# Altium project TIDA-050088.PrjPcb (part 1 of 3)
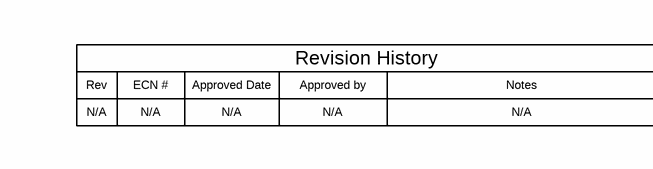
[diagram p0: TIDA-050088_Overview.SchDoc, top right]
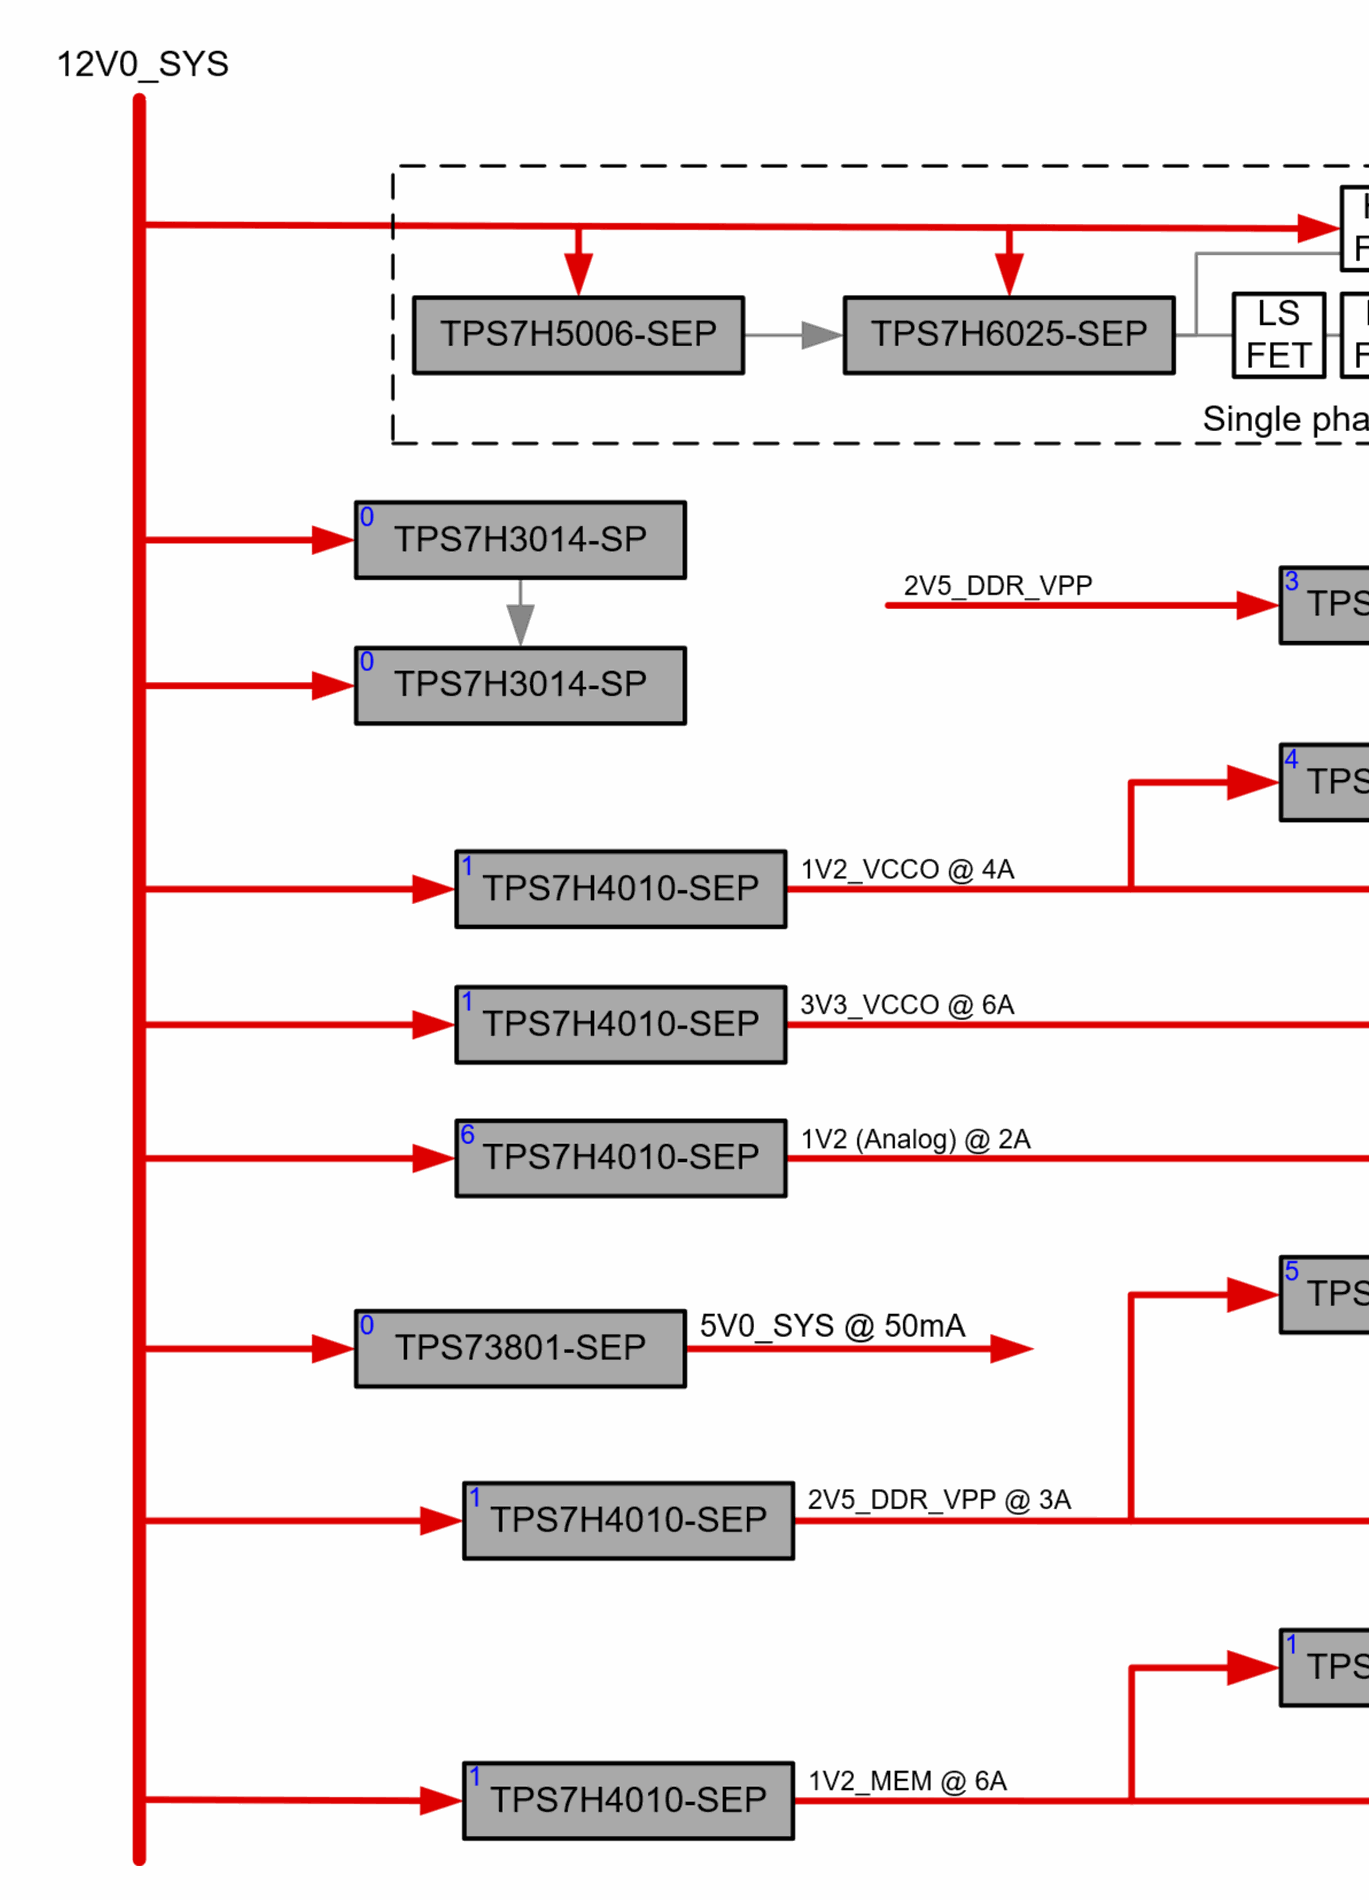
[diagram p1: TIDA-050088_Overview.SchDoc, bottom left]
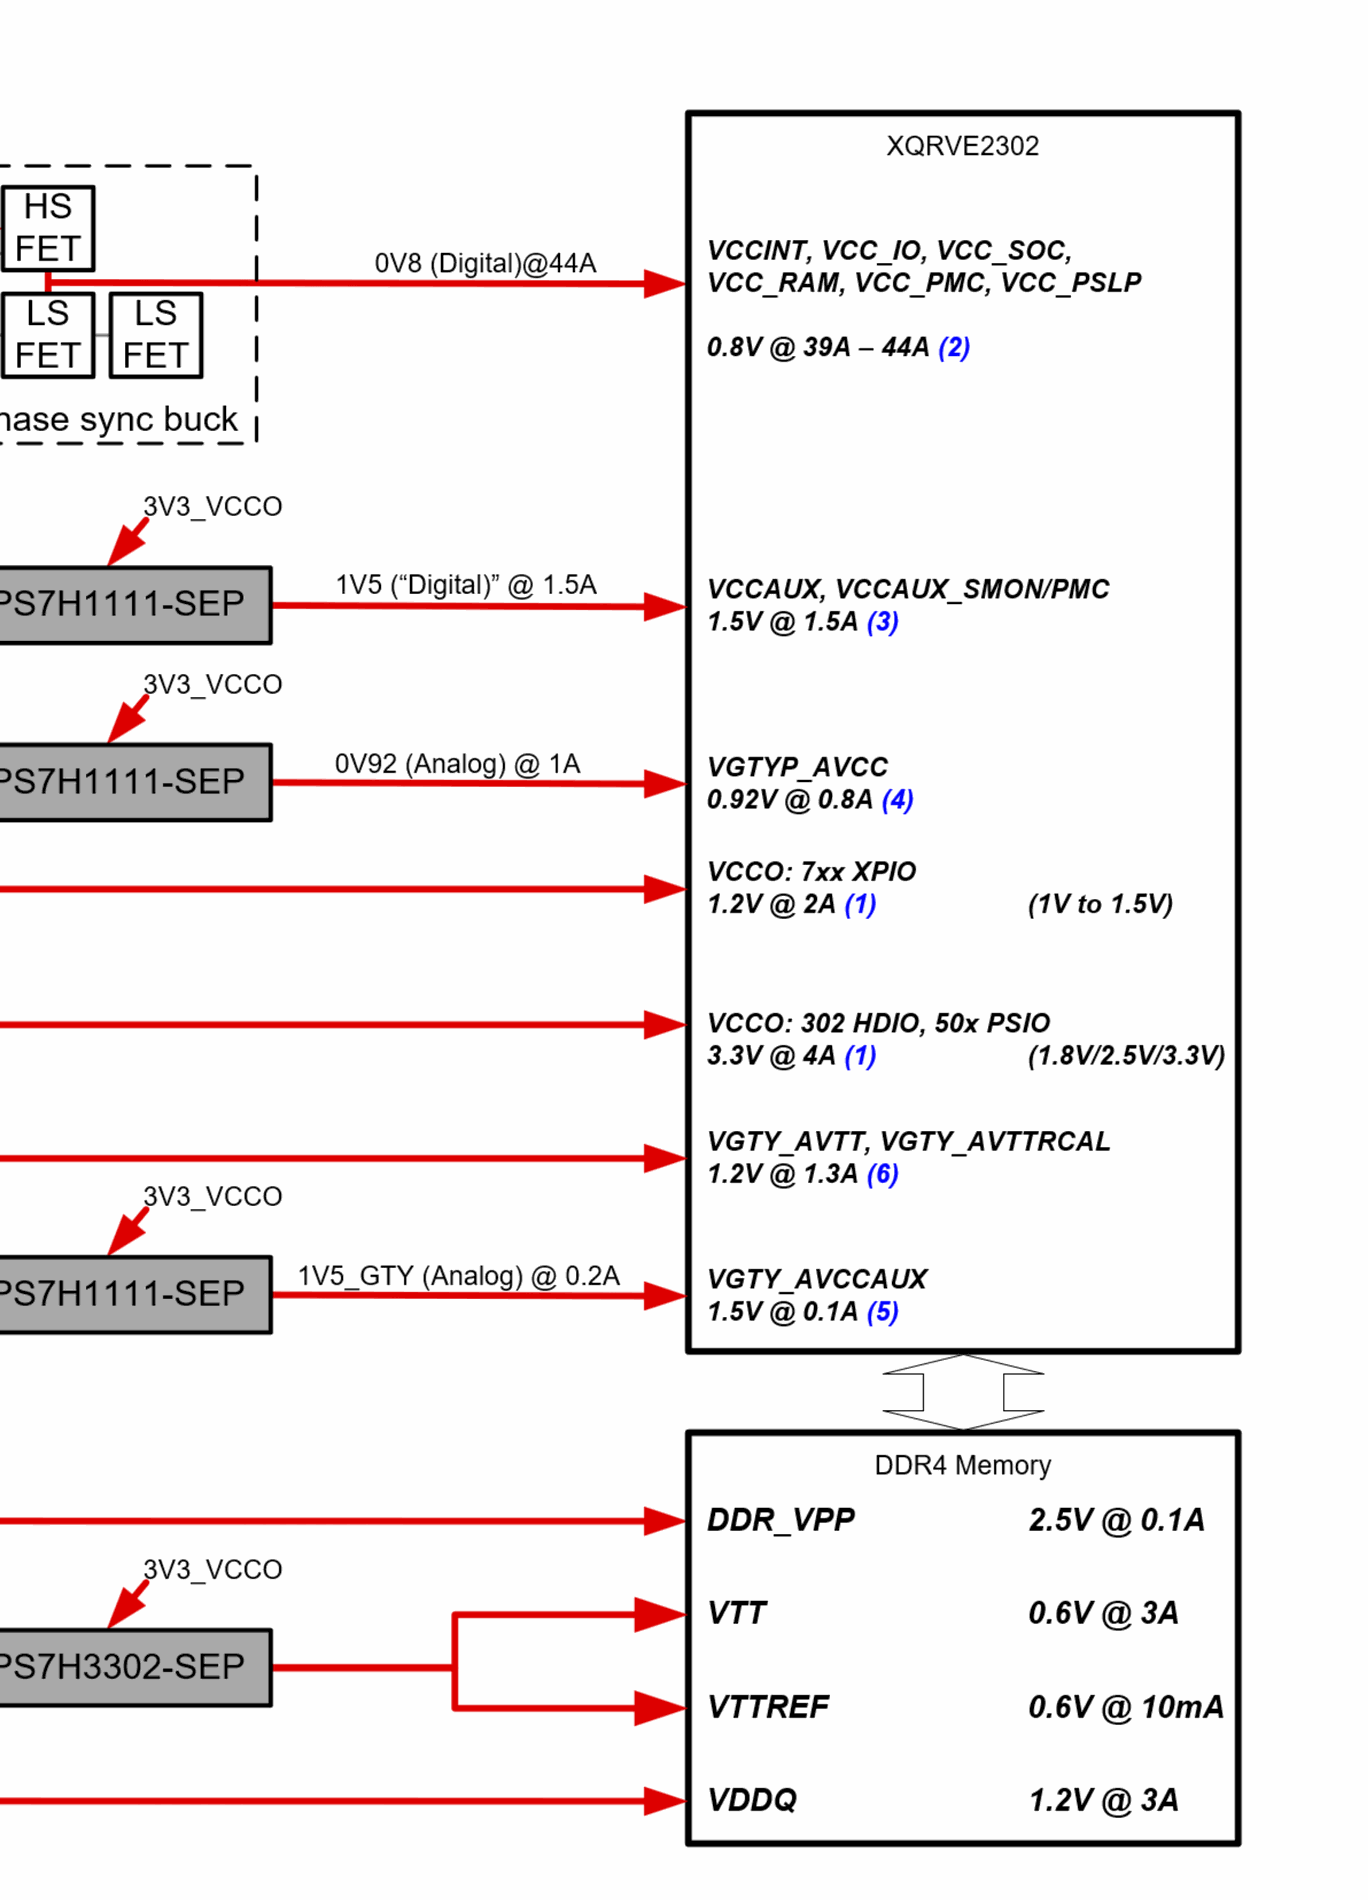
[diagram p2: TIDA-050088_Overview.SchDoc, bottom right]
CopyrightYear: 2024; DrawnBy: Kyle Rakos; PCB_Layout: Kyle Rakos; PCB_Rev: A; PRJ_Customer: Public Release; PRJ_Engineer: Kyle Rakos; PRJ_Number: TIDA-050088; PRJ_Title: Versal AI Edge XQRVE2302 Power; SCH_Rev: A; TechSupport: http://www.ti.com/support; TID: 050088; Versal AI Edge XQRVE2302 Power: EdgePower
7 sheets, 539 parts. Net scope: global (net labels, ports and power ports of the same name join across sheets).
Board file: TIDA-050088_PCB.PcbDoc
Sheets:
  TIDA-050088_Overview.SchDoc
  TIDA-050088_Core.SchDoc
  TIDA-050088_Sequencing.SchDoc
  TIDA-050088_LDOs.SchDoc
  TIDA-050088_Bucks.SchDoc
  TIDA-050088_Aux.SchDoc
  TIDA-050088_Hardware.SchDoc

## Sheet TIDA-050088_Overview.SchDoc
size 558 x 431 mm; Date: Not shown in title block; ApprovedBy: Not shown in title block; CheckedBy: Not shown in title block; Author: Not shown in title block; CompanyName: Not shown in title block; Engineer: Not shown in title block; Organization: Not shown in title block; Address1: Not shown in title block; Address2: Not shown in title block; Address3: Not shown in title block; Address4: Not shown in title block; DocumentNumber: 1; Revision: Use project parameter SCH_Rev; SheetNumber: 1; SheetTotal: 7; PageSetup: Record=PageOptions¦CenterHorizontal=True¦CenterVertical=True¦PrintScale=1.00¦XCorrection=1.00¦YCorrection=1.00¦PrintKind=0¦BorderSize=5000000¦LeftOffset=0¦BottomOffset=0¦Orientation=2¦PaperLength=1000¦PaperWidth=1000¦Scale=100¦PaperSource=15¦PrintQuality=600¦MediaType=1¦DitherType=10¦PaperKind=Letter¦PrintScaleMode=1

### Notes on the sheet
- Rev
- N/A
- ECN #
- Approved Date
- Approved by
- Revision History
- Notes

## Sheet TIDA-050088_Core.SchDoc
size 558 x 431 mm; Date: Not shown in title block; ApprovedBy: Not shown in title block; CheckedBy: Not shown in title block; Author: Not shown in title block; CompanyName: Not shown in title block; Engineer: Not shown in title block; Organization: Not shown in title block; Address1: Not shown in title block; Address2: Not shown in title block; Address3: Not shown in title block; Address4: Not shown in title block; DocumentNumber: 2; Revision: Use project parameter SCH_Rev; SheetNumber: 2; SheetTotal: 7; PageSetup: Record=PageOptions¦CenterHorizontal=True¦CenterVertical=True¦PrintScale=1.00¦XCorrection=1.00¦YCorrection=1.00¦PrintKind=0¦BorderSize=5000000¦LeftOffset=0¦BottomOffset=0¦Orientation=2¦PaperLength=1000¦PaperWidth=1000¦Scale=100¦PaperSource=15¦PrintQuality=600¦MediaType=1¦DitherType=10¦PaperKind=Letter¦PrintScaleMode=1
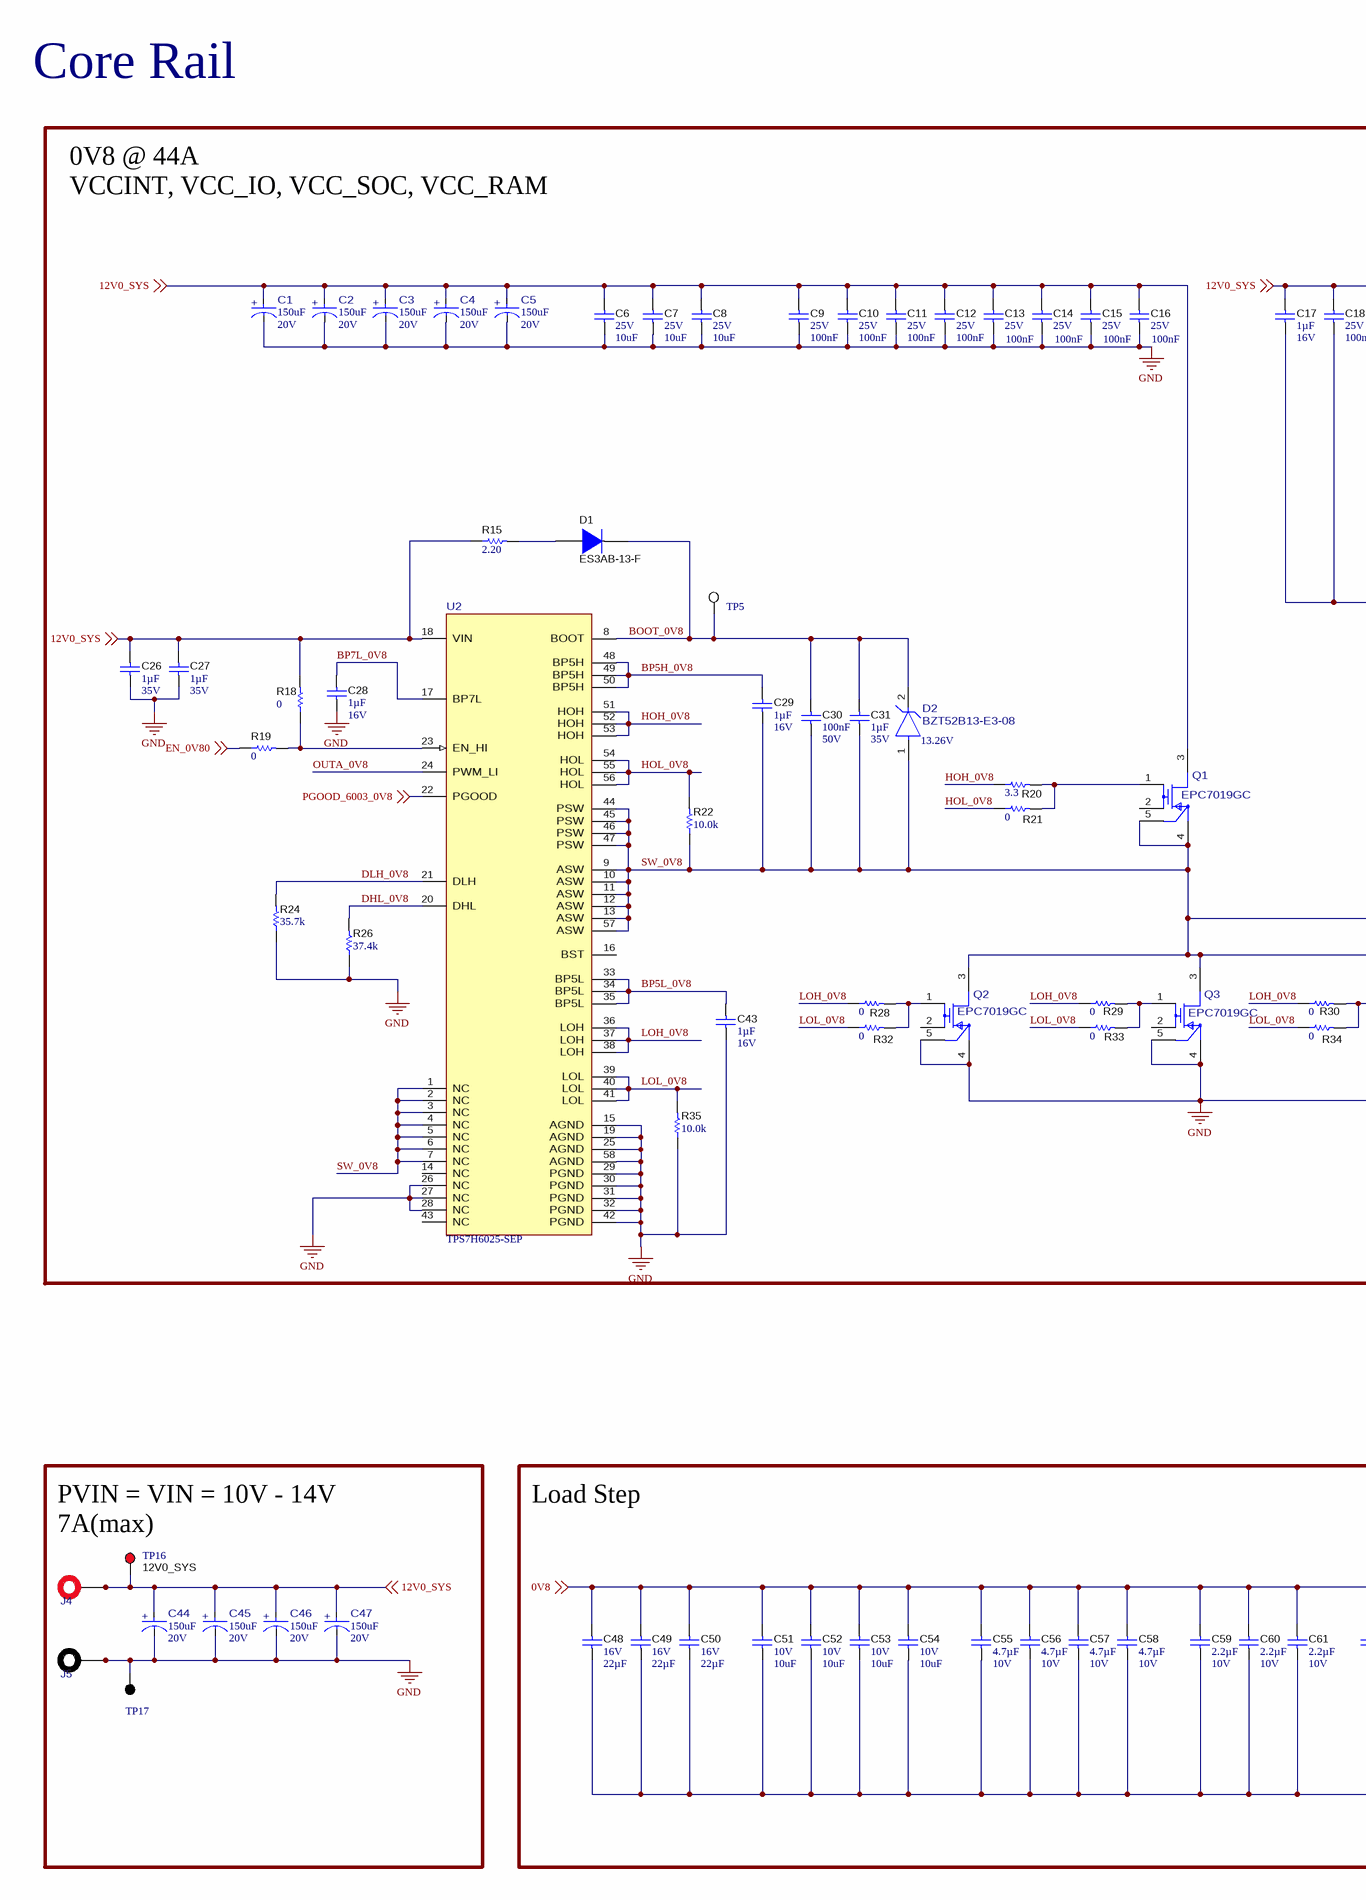
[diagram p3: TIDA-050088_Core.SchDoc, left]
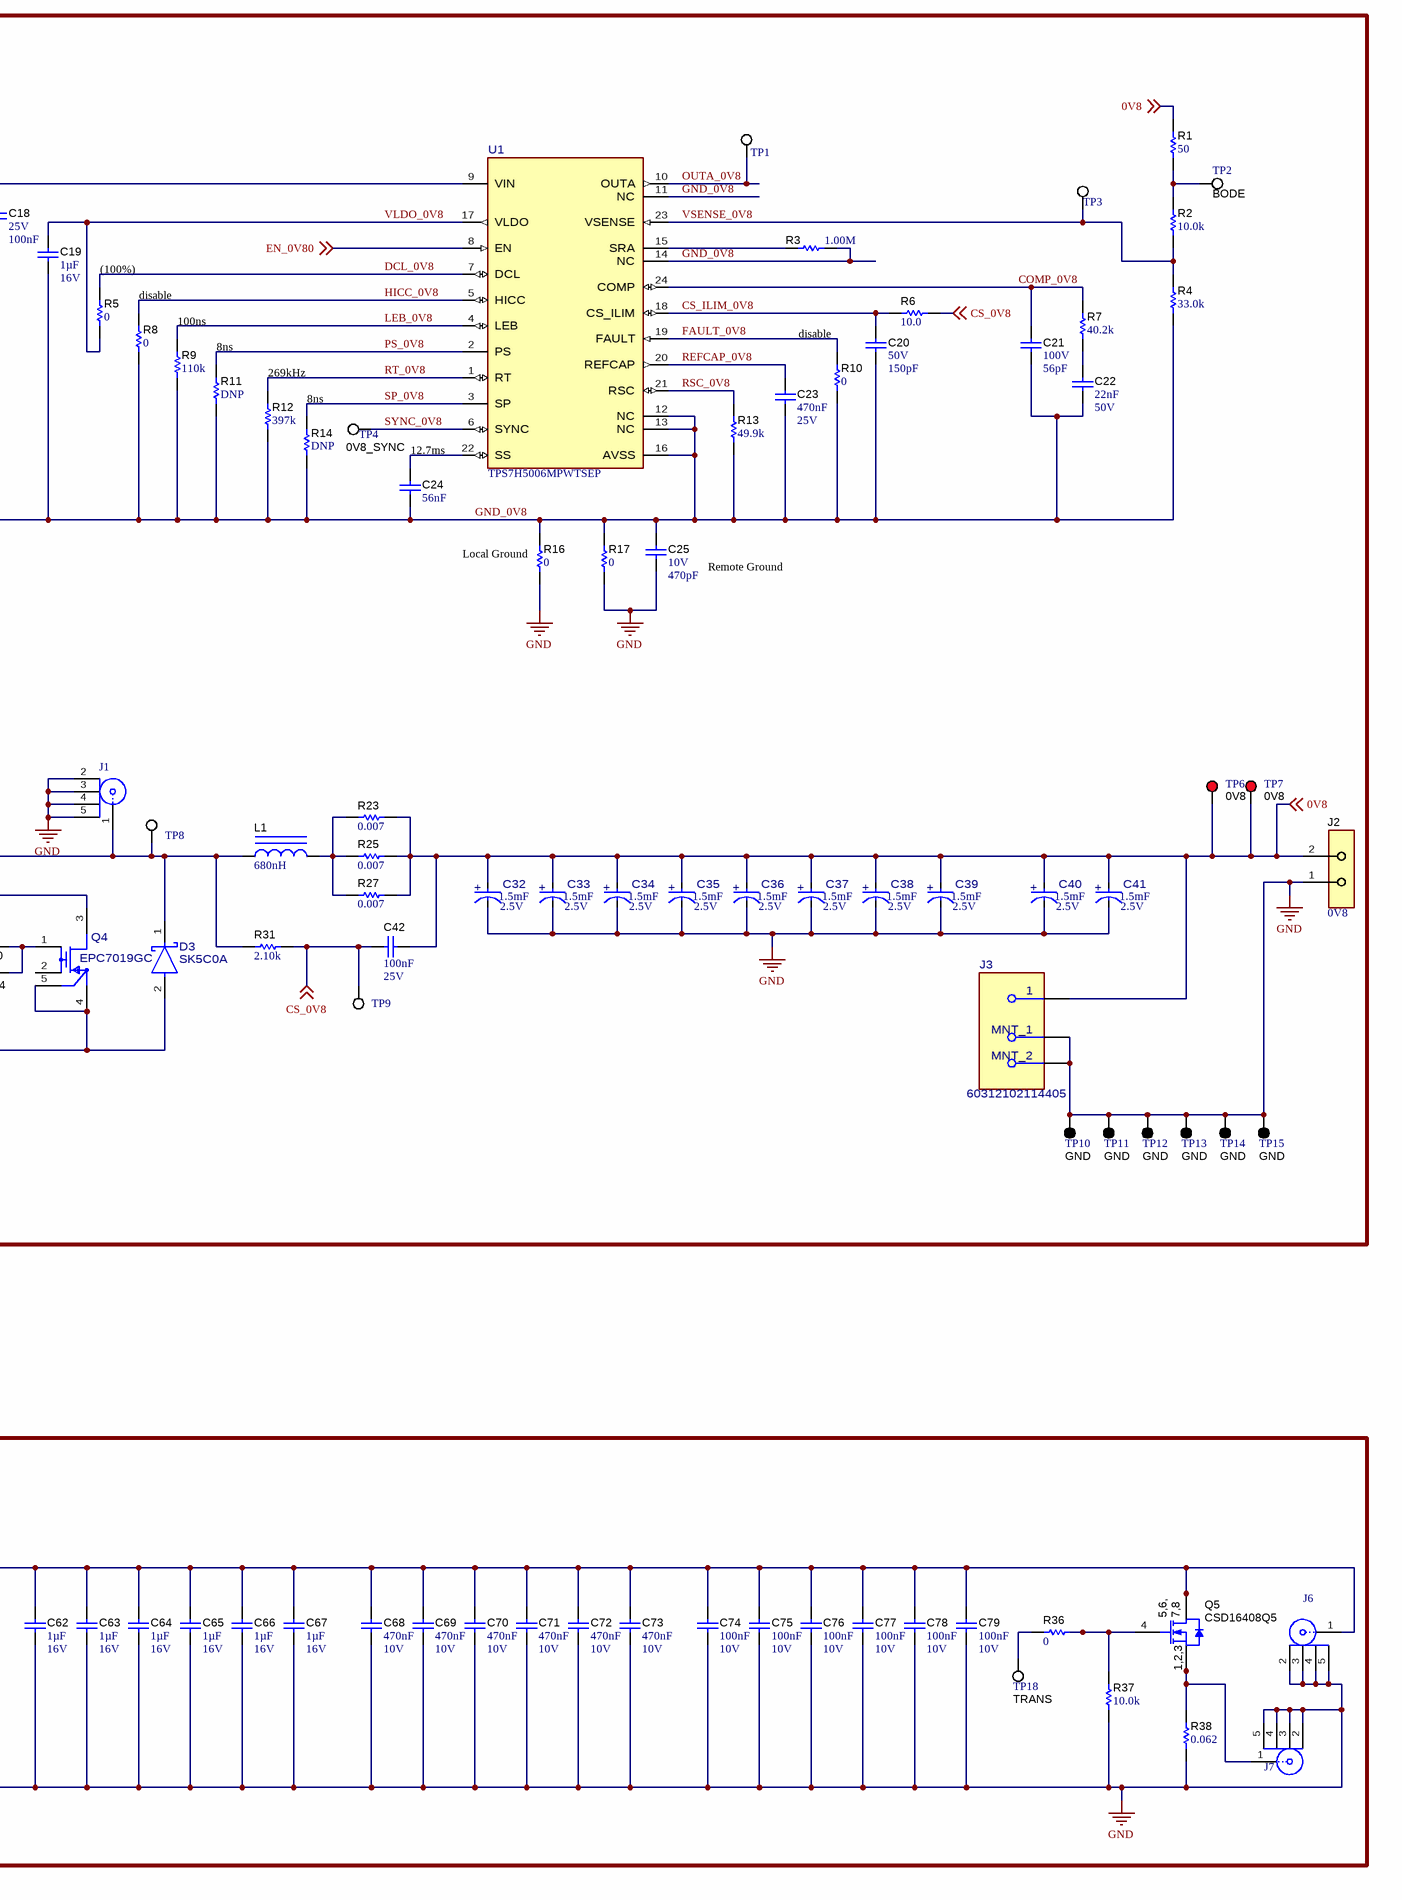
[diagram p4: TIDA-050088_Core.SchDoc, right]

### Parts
C1  ValueDisplayed: 150uF  VDC_V: 20V  [FP-T521D157M020ATE050_2917-MFG]  (hidden comment: T521D157M020ATE050)
C2  ValueDisplayed: 150uF  VDC_V: 20V  [FP-T521D157M020ATE050_2917-MFG]  (hidden comment: T521D157M020ATE050)
C3  ValueDisplayed: 150uF  VDC_V: 20V  [FP-T521D157M020ATE050_2917-MFG]  (hidden comment: T521D157M020ATE050)
C4  ValueDisplayed: 150uF  VDC_V: 20V  [FP-T521D157M020ATE050_2917-MFG]  (hidden comment: T521D157M020ATE050)
C5  ValueDisplayed: 150uF  VDC_V: 20V  [FP-T521D157M020ATE050_2917-MFG]  (hidden comment: T521D157M020ATE050)
C6  VDC_V: 25V  ValueDisplayed: 10uF  [1210_280]  (hidden comment: GCM32ER71E106KA57L)
C7  VDC_V: 25V  ValueDisplayed: 10uF  [1210_280]  (hidden comment: GCM32ER71E106KA57L)
C8  VDC_V: 25V  ValueDisplayed: 10uF  [1210_280]  (hidden comment: GCM32ER71E106KA57L)
C9  VDC_V: 25V  Cap_F: 100nF  [0603]  (hidden comment: GCM188R71E104KA57D)
C10  VDC_V: 25V  Cap_F: 100nF  [0603]  (hidden comment: GCM188R71E104KA57D)
C11  VDC_V: 25V  Cap_F: 100nF  [0603]  (hidden comment: GCM188R71E104KA57D)
C12  VDC_V: 25V  Cap_F: 100nF  [0603]  (hidden comment: GCM188R71E104KA57D)
C13  VDC_V: 25V  Cap_F: 100nF  [0603]  (hidden comment: GCM188R71E104KA57D)
C14  VDC_V: 25V  Cap_F: 100nF  [0603]  (hidden comment: GCM188R71E104KA57D)
C15  VDC_V: 25V  Cap_F: 100nF  [0603]  (hidden comment: GCM188R71E104KA57D)
C16  VDC_V: 25V  Cap_F: 100nF  [0603]  (hidden comment: GCM188R71E104KA57D)
C17  Cap_F: 1µF  VDC_V: 16V  [0805_HV]  (hidden comment: C0805C105K4RACAUTO)
C18  VDC_V: 25V  Cap_F: 100nF  [0603]  (hidden comment: GCM188R71E104KA57D)
C19  Cap_F: 1µF  VDC_V: 16V  [0805_HV]  (hidden comment: C0805C105K4RACAUTO)
C20  VDC_V: 50V  ValueDisplayed: 150pF  [0603]  (hidden comment: C0603C151J5GACTU)
C21  VDC_V: 100V  ValueDisplayed: 56pF  [0603]  (hidden comment: GRM1885C2A560JA01D)
C22  Cap_F: 22nF  VDC_V: 50V  [0603]  (hidden comment: C0603C223K5RACTU)
C23  Cap_F: 470nF  VDC_V: 25V  [0603]  (hidden comment: GCM188R71E474KA64D)
C24  Cap_F: 56nF  [0603]  (hidden comment: 06035C563KAT2A)
C25  VDC_V: 10V  ValueDisplayed: 470pF  [0603]  (hidden comment: 885012006012)
C26  Cap_F: 1µF  VDC_V: 35V  [0805_HV]  (hidden comment: GRM219R7YA105KA12D)
C27  Cap_F: 1µF  VDC_V: 35V  [0805_HV]  (hidden comment: GRM219R7YA105KA12D)
C28  Cap_F: 1µF  VDC_V: 16V  [0805_HV]  (hidden comment: C0805C105K4RACAUTO)
C29  Cap_F: 1µF  VDC_V: 16V  [0805_HV]  (hidden comment: C0805C105K4RACAUTO)
C30  Cap_F: 100nF  VDC_V: 50V  [0603]  (hidden comment: 06035C104KAZ2A)
C31  Cap_F: 1µF  VDC_V: 35V  [0805_HV]  (hidden comment: GRM219R7YA105KA12D)
C32  ValueDisplayed: 1.5mF  VDC_V: 2.5V  [FP-T520X158M2R5ATE015_2917-MFG]  (hidden comment: T520X158M2R5ATE015)
C33  ValueDisplayed: 1.5mF  VDC_V: 2.5V  [FP-T520X158M2R5ATE015_2917-MFG]  (hidden comment: T520X158M2R5ATE015)
C34  ValueDisplayed: 1.5mF  VDC_V: 2.5V  [FP-T520X158M2R5ATE015_2917-MFG]  (hidden comment: T520X158M2R5ATE015)
C35  ValueDisplayed: 1.5mF  VDC_V: 2.5V  [FP-T520X158M2R5ATE015_2917-MFG]  (hidden comment: T520X158M2R5ATE015)
C36  ValueDisplayed: 1.5mF  VDC_V: 2.5V  [FP-T520X158M2R5ATE015_2917-MFG]  (hidden comment: T520X158M2R5ATE015)
C37  ValueDisplayed: 1.5mF  VDC_V: 2.5V  [FP-T520X158M2R5ATE015_2917-MFG]  (hidden comment: T520X158M2R5ATE015)
C38  ValueDisplayed: 1.5mF  VDC_V: 2.5V  [FP-T520X158M2R5ATE015_2917-MFG]  (hidden comment: T520X158M2R5ATE015)
C39  ValueDisplayed: 1.5mF  VDC_V: 2.5V  [FP-T520X158M2R5ATE015_2917-MFG]  (hidden comment: T520X158M2R5ATE015)
C40  ValueDisplayed: 1.5mF  VDC_V: 2.5V  [FP-T520X158M2R5ATE015_2917-MFG]  (hidden comment: T520X158M2R5ATE015)
C41  ValueDisplayed: 1.5mF  VDC_V: 2.5V  [FP-T520X158M2R5ATE015_2917-MFG]  (hidden comment: T520X158M2R5ATE015)
C42  Cap_F: 100nF  VDC_V: 25V  [0603]  (hidden comment: C0603X104K3RACTU)
C43  Cap_F: 1µF  VDC_V: 16V  [0805_HV]  (hidden comment: C0805C105K4RACAUTO)
C44  ValueDisplayed: 150uF  VDC_V: 20V  [FP-T521D157M020ATE050_2917-MFG]  (hidden comment: T521D157M020ATE050)
C45  ValueDisplayed: 150uF  VDC_V: 20V  [FP-T521D157M020ATE050_2917-MFG]  (hidden comment: T521D157M020ATE050)
C46  ValueDisplayed: 150uF  VDC_V: 20V  [FP-T521D157M020ATE050_2917-MFG]  (hidden comment: T521D157M020ATE050)
C47  ValueDisplayed: 150uF  VDC_V: 20V  [FP-T521D157M020ATE050_2917-MFG]  (hidden comment: T521D157M020ATE050)
C48  VDC_V: 16V  ValueDisplayed: 22µF  [1210_270]  (hidden comment: CL32B226KOJNFNE)
C49  VDC_V: 16V  ValueDisplayed: 22µF  [1210_270]  (hidden comment: CL32B226KOJNFNE)
C50  VDC_V: 16V  ValueDisplayed: 22µF  [1210_270]  (hidden comment: CL32B226KOJNFNE)
C51  VDC_V: 10V  ValueDisplayed: 10uF  [1206]  (hidden comment: C3216X7R1A106K085AC)
C52  VDC_V: 10V  ValueDisplayed: 10uF  [1206]  (hidden comment: C3216X7R1A106K085AC)
C53  VDC_V: 10V  ValueDisplayed: 10uF  [1206]  (hidden comment: C3216X7R1A106K085AC)
C54  VDC_V: 10V  ValueDisplayed: 10uF  [1206]  (hidden comment: C3216X7R1A106K085AC)
C55  Cap_F: 4.7µF  VDC_V: 10V  [0805_HV]  (hidden comment: 885012207025)
C56  Cap_F: 4.7µF  VDC_V: 10V  [0805_HV]  (hidden comment: 885012207025)
C57  Cap_F: 4.7µF  VDC_V: 10V  [0805_HV]  (hidden comment: 885012207025)
C58  Cap_F: 4.7µF  VDC_V: 10V  [0805_HV]  (hidden comment: 885012207025)
C59  Cap_F: 2.2µF  VDC_V: 10V  [0805_HV]  (hidden comment: GRM21BR71A225KA01L)
C60  Cap_F: 2.2µF  VDC_V: 10V  [0805_HV]  (hidden comment: GRM21BR71A225KA01L)
C61  Cap_F: 2.2µF  VDC_V: 10V  [0805_HV]  (hidden comment: GRM21BR71A225KA01L)
C62  Cap_F: 1µF  VDC_V: 16V  [0805_HV]  (hidden comment: C0805C105K4RACAUTO)
C63  Cap_F: 1µF  VDC_V: 16V  [0805_HV]  (hidden comment: C0805C105K4RACAUTO)
C64  Cap_F: 1µF  VDC_V: 16V  [0805_HV]  (hidden comment: C0805C105K4RACAUTO)
C65  Cap_F: 1µF  VDC_V: 16V  [0805_HV]  (hidden comment: C0805C105K4RACAUTO)
C66  Cap_F: 1µF  VDC_V: 16V  [0805_HV]  (hidden comment: C0805C105K4RACAUTO)
C67  Cap_F: 1µF  VDC_V: 16V  [0805_HV]  (hidden comment: C0805C105K4RACAUTO)
C68  Cap_F: 470nF  VDC_V: 10V  [0603]  (hidden comment: C0603C474K8RACTU)
C69  Cap_F: 470nF  VDC_V: 10V  [0603]  (hidden comment: C0603C474K8RACTU)
C70  Cap_F: 470nF  VDC_V: 10V  [0603]  (hidden comment: C0603C474K8RACTU)
C71  Cap_F: 470nF  VDC_V: 10V  [0603]  (hidden comment: C0603C474K8RACTU)
C72  Cap_F: 470nF  VDC_V: 10V  [0603]  (hidden comment: C0603C474K8RACTU)
C73  Cap_F: 470nF  VDC_V: 10V  [0603]  (hidden comment: C0603C474K8RACTU)
C74  Cap_F: 100nF  VDC_V: 10V  [0603]  (hidden comment: 885012206020)
C75  Cap_F: 100nF  VDC_V: 10V  [0603]  (hidden comment: 885012206020)
C76  Cap_F: 100nF  VDC_V: 10V  [0603]  (hidden comment: 885012206020)
C77  Cap_F: 100nF  VDC_V: 10V  [0603]  (hidden comment: 885012206020)
C78  Cap_F: 100nF  VDC_V: 10V  [0603]  (hidden comment: 885012206020)
C79  Cap_F: 100nF  VDC_V: 10V  [0603]  (hidden comment: 885012206020)
D1  ES3AB-13-F  [SMB]
D2  BZT52B13-E3-08  Vf_V: 13.26V  [FP-BZT52B13-E3-08_SOD123-MFG]
D3  SK5C0A  [FP-SK5C0A_SMA-MFG]
J1  SW  [Tek_131-5031-00]  (value not drawn)
J2  Silkscreen: 0V8  [FP-1929517_HDR2-MFG]  (hidden comment: 1929517)
J3  60312102114405  [FP-60312102114405_CONN_SMA-MFG]
J4  571-0500  [571-0500]  (value not drawn)
J5  571-0100  [571-0100]  (value not drawn)
J6  0V8  [Tek_131-5031-00]  (value not drawn)
J7  ISTEP  [Tek_131-5031-00]  (value not drawn)
L1  ValueDisplayed: 680nH  [XAL1010]  (hidden comment: XAL1010-681MEB)
Q1  EPC7019GC  [FP-EPC7019GC_FSMD-G-MFG]
Q2  EPC7019GC  [FP-EPC7019GC_FSMD-G-MFG]
Q3  EPC7019GC  [FP-EPC7019GC_FSMD-G-MFG]
Q4  EPC7019GC  [FP-EPC7019GC_FSMD-G-MFG]
Q5  CSD16408Q5  [DQH0008A]
R1  ValueDisplayed: 50  [0603]  (hidden comment: FC0603E50R0BTBST1)
R2  ValueDisplayed: 10.0k  [0603]  (hidden comment: PHT0603Y1002BGT200)
R3  ValueDisplayed: 1.00M  [0603]  (hidden comment: CRCW06031M00FKEA)
R4  ValueDisplayed: 33.0k  [0603]  (hidden comment: RG1608P-333-B-T5)
R5  ValueDisplayed: 0  [0603]  (hidden comment: RCS06030000Z0EA)
R6  ValueDisplayed: 10.0  [0603]  (hidden comment: TNPW060310R0BEEA)
R7  ValueDisplayed: 40.2k  [0603]  (hidden comment: RT0603BRD0740K2L)
R8  ValueDisplayed: 0  [0603]  (hidden comment: RCS06030000Z0EA)
R9  ValueDisplayed: 110k  [0603]  (hidden comment: RG1608P-114-B-T5)
R10  ValueDisplayed: 0  [0603]  (hidden comment: RCS06030000Z0EA)
R11  ValueDisplayed: DNP  [0603]  (hidden comment: RN73H1JTTD3973F25)
R12  ValueDisplayed: 397k  [0603]  (hidden comment: RN73H1JTTD3973F25)
R13  ValueDisplayed: 49.9k  [0603]  (hidden comment: RT0603BRD0749K9L)
R14  ValueDisplayed: DNP  [0603]  (hidden comment: RN73H1JTTD3973F25)
R15  ValueDisplayed: 2.20  [0603]  (hidden comment: ERJ-3RQF2R2V)
R16  ValueDisplayed: 0  [0603]  (hidden comment: RCS06030000Z0EA)
R17  ValueDisplayed: 0  [0603]  (hidden comment: RCS06030000Z0EA)
R18  ValueDisplayed: 0  [0603]  (hidden comment: RCS06030000Z0EA)
R19  ValueDisplayed: 0  [0603]  (hidden comment: RCS06030000Z0EA)
R20  ValueDisplayed: 3.3  [0603]  (hidden comment: CRCW06033R30JNEA)
R21  ValueDisplayed: 0  [0603]  (hidden comment: RCS06030000Z0EA)
R22  ValueDisplayed: 10.0k  [0603]  (hidden comment: PHT0603Y1002BGT200)
R23  ValueDisplayed: 0.007  [2512_WIDE]  (hidden comment: KRL6432E-M-R007-F-T1)
R24  ValueDisplayed: 35.7k  [0603]  (hidden comment: RT0603BRD0735K7L)
R25  ValueDisplayed: 0.007  [2512_WIDE]  (hidden comment: KRL6432E-M-R007-F-T1)
R26  ValueDisplayed: 37.4k  [0603]  (hidden comment: RT0603BRD0737K4L)
R27  ValueDisplayed: 0.007  [2512_WIDE]  (hidden comment: KRL6432E-M-R007-F-T1)
R28  ValueDisplayed: 0  [0603]  (hidden comment: RCS06030000Z0EA)
R29  ValueDisplayed: 0  [0603]  (hidden comment: RCS06030000Z0EA)
R30  ValueDisplayed: 0  [0603]  (hidden comment: RCS06030000Z0EA)
R31  ValueDisplayed: 2.10k  [0603]  (hidden comment: RG1608P-2101-B-T5)
R32  ValueDisplayed: 0  [0603]  (hidden comment: RCS06030000Z0EA)
R33  ValueDisplayed: 0  [0603]  (hidden comment: RCS06030000Z0EA)
R34  ValueDisplayed: 0  [0603]  (hidden comment: RCS06030000Z0EA)
R35  ValueDisplayed: 10.0k  [0603]  (hidden comment: PHT0603Y1002BGT200)
R36  ValueDisplayed: 0  [0603]  (hidden comment: RCS06030000Z0EA)
R37  ValueDisplayed: 10.0k  [0603]  (hidden comment: PHT0603Y1002BGT200)
R38  ValueDisplayed: 0.062  [2512_084]  (hidden comment: PE2512FKF7W0R062L)
TP1  OUTA  [Keystone5012]  (value not drawn)
TP2  BODE  [Keystone5012]
TP3  VSNS  [Keystone5012]  (value not drawn)
TP4  0V8_SYNC  [Keystone5012]
TP5  BOOT  [Keystone5012]  (value not drawn)
TP6  0V8  [Keystone5010]
TP7  0V8  [Keystone5010]
TP8  SW  [Keystone5012]  (value not drawn)
TP9  CS  [Keystone5012]  (value not drawn)
TP10  GND  [Keystone5011]
TP11  GND  [Keystone5011]
TP12  GND  [Keystone5011]
TP13  GND  [Keystone5011]
TP14  GND  [Keystone5011]
TP15  GND  [Keystone5011]
TP16  12V0_SYS  [Keystone5010]
TP17  GND  [Keystone5011]  (value not drawn)
TP18  TRANS  [Keystone5012]
U1  TPS7H5006MPWTSEP  [PW0024A-MFG]
U2  PartNumber: TPS7H6025-SEP  [DCA0056M-MFG]  (hidden comment: PTPS7H6025-SEP)

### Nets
GND: C1.1(CATHODE) C2.1(CATHODE) C3.1(CATHODE) C4.1(CATHODE) C5.1(CATHODE) C6.2 C7.2 C8.2 C9.2 C10.2 C11.2 C12.2 C13.2 C14.2 C15.2 C16.2 C25.2 C26.2 C27.2 C28.2 C32.1(CATHODE) C33.1(CATHODE) C34.1(CATHODE) C35.1(CATHODE) C36.1(CATHODE) C37.1(CATHODE) C38.1(CATHODE) C39.1(CATHODE) C40.1(CATHODE) C41.1(CATHODE) C43.2 C44.1(CATHODE) C45.1(CATHODE) C46.1(CATHODE) C47.1(CATHODE) C48.2 C49.2 C50.2 C51.2 C52.2 C53.2 C54.2 C55.2 C56.2 C57.2 C58.2 C59.2 C60.2 C61.2 C62.2 C63.2 C64.2 C65.2 C66.2 C67.2 C68.2 C69.2 C70.2 C71.2 C72.2 C73.2 C74.2 C75.2 C76.2 C77.2 C78.2 C79.2 D3.2(ANODE) J1.2 J1.3 J1.4 J1.5 J2.1 J3.2(MNT_1) J3.3(MNT_2) J5.1 J5.2 J6.2 J6.3 J6.4 J6.5 J7.2 J7.3 J7.4 J7.5 Q2.4(S) Q2.5(SS) Q3.4(S) Q3.5(SS) Q4.4(S) Q4.5(SS) R16.1 R17.1 R24.1 R26.1 R35.1 R37.1 R38.1 TP10.1 TP11.1 TP12.1 TP13.1 TP14.1 TP15.1 TP17.1 U2.15(AGND) U2.19(AGND) U2.25(AGND) U2.26(NC) U2.27(NC) U2.28(NC) U2.29(PGND) U2.30(PGND) U2.31(PGND) U2.32(PGND) U2.42(PGND) U2.58(AGND)
0V8: C32.2(ANODE) C33.2(ANODE) C34.2(ANODE) C35.2(ANODE) C36.2(ANODE) C37.2(ANODE) C38.2(ANODE) C39.2(ANODE) C40.2(ANODE) C41.2(ANODE) C42.1 C48.1 C49.1 C50.1 C51.1 C52.1 C53.1 C54.1 C55.1 C56.1 C57.1 C58.1 C59.1 C60.1 C61.1 C62.1 C63.1 C64.1 C65.1 C66.1 C67.1 C68.1 C69.1 C70.1 C71.1 C72.1 C73.1 C74.1 C75.1 C76.1 C77.1 C78.1 C79.1 J2.2 J3.1 J6.1 Q5.5(D) Q5.6(D) Q5.7(D) Q5.8(D) Q5.9(D) R1.2 R23.2 R25.2 R27.2 TP6.1 TP7.1 ; off-sheet 0V8
12V0_SYS: C1.2(ANODE) C2.2(ANODE) C3.2(ANODE) C4.2(ANODE) C5.2(ANODE) C6.1 C7.1 C8.1 C9.1 C10.1 C11.1 C12.1 C13.1 C14.1 C15.1 C16.1 C17.1 C18.1 C26.1 C27.1 C44.2(ANODE) C45.2(ANODE) C46.2(ANODE) C47.2(ANODE) J4.1 J4.2 Q1.3(D) R15.1 R18.2 TP16.1 U1.9(VIN) U2.18(VIN) ; off-sheet 12V0_SYS
BOOT_0V8: C30.1 C31.1 D1.1(K) D2.2(CATHODE) TP5.1 U2.8(BOOT)
BP5H_0V8: C29.1 U2.48(BP5H) U2.49(BP5H) U2.50(BP5H)
BP5L_0V8: C43.1 U2.33(BP5L) U2.34(BP5L) U2.35(BP5L)
BP7L_0V8: C28.1 U2.17(BP7L)
COMP_0V8: C21.1 R7.2 U1.24(COMP)
CS_0V8: C42.2 R6.2 R31.2 TP9.1 ; off-sheet CS_0V8
CS_ILIM_0V8: C20.1 R6.1 U1.18(CS_ILIM)
DCL_0V8: R5.2 U1.7(DCL)
DHL_0V8: R26.2 U2.20(DHL)
DLH_0V8: R24.2 U2.21(DLH)
EN_0V80: R19.1 U1.8(EN) ; off-sheet EN_0V80
FAULT_0V8: R10.2 U1.19(FAULT)
GND_0V8: C17.2 C18.2 C19.2 C20.2 C21.2 C22.2 C23.2 C24.2 C25.1 R3.2 R4.1 R8.1 R9.1 R10.1 R11.1 R12.1 R13.1 R14.1 R16.2 R17.2 U1.11(NC) U1.12(NC) U1.13(NC) U1.14(NC) U1.16(AVSS)
HICC_0V8: R8.2 U1.5(HICC)
HOH_0V8: R20.1 U2.51(HOH) U2.52(HOH) U2.53(HOH)
HOL_0V8: R21.1 R22.2 U2.54(HOL) U2.55(HOL) U2.56(HOL)
LEB_0V8: R9.2 U1.4(LEB)
LOH_0V8: R28.1 R29.1 R30.1 U2.36(LOH) U2.37(LOH) U2.38(LOH)
LOL_0V8: R32.1 R33.1 R34.1 R35.2 U2.39(LOL) U2.40(LOL) U2.41(LOL)
OUTA_0V8: TP1.1 U1.10(OUTA) U2.24(PWM_LI)
PGOOD_6003_0V8: U2.22(PGOOD) ; off-sheet PGOOD_6003_0V8
PS_0V8: R11.2 U1.2(PS)
REFCAP_0V8: C23.1 U1.20(REFCAP)
RSC_0V8: R13.2 U1.21(RSC)
RT_0V8: R12.2 U1.1(RT)
SP_0V8: R14.2 U1.3(SP)
SW_0V8: C29.2 C30.2 C31.2 D2.1(ANODE) D3.1(CATHODE) J1.1 L1.1 Q1.4(S) Q1.5(SS) Q2.3(D) Q3.3(D) Q4.3(D) R22.1 R31.1 TP8.1 U2.1(NC) U2.2(NC) U2.3(NC) U2.4(NC) U2.5(NC) U2.6(NC) U2.7(NC) U2.9(ASW) U2.10(ASW) U2.11(ASW) U2.12(ASW) U2.13(ASW) U2.44(PSW) U2.45(PSW) U2.46(PSW) U2.47(PSW) U2.57(ASW)
SYNC_0V8: TP4.1 U1.6(SYNC)
VLDO_0V8: C19.1 R5.1 U1.17(VLDO)
VSENSE_0V8: R2.1 R4.2 TP3.1 U1.23(VSENSE)
NetC22_1: C22.1 R7.1
NetC24_1: C24.1 U1.22(SS)
NetD1_2: D1.2(A) R15.2
NetJ7_1: J7.1 Q5.1(S) Q5.2(S) Q5.3(S) R38.2
NetL1_2: L1.2 R23.1 R25.1 R27.1
NetQ1_1: Q1.1(G) R20.2 R21.2
NetQ2_1: Q2.1(G) R28.2 R32.2
NetQ3_1: Q3.1(G) R29.2 R33.2
NetQ4_1: Q4.1(G) R30.2 R34.2
NetQ5_4: Q5.4(G) R36.2 R37.2
NetR1_1: R1.1 R2.2 TP2.1
NetR3_1: R3.1 U1.15(SRA)
NetR18_1: R18.1 R19.2 U2.23(EN_HI)
NetR36_1: R36.1 TP18.1

Not connected (* = marked no-connect by the designer): Q1 2(G); Q2 2(G); Q3 2(G); Q4 2(G); U2 14(NC) 16(BST) 43(NC)

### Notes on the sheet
- Core Rail
- 0V8 @ 44A
  VCCINT, VCC_IO, VCC_SOC, VCC_RAM
- (near R5) (100%)
- disable
- 100ns
- 8ns
- (near R12) 269kHz
- 12.7ms
- (near R16) Local Ground
- Remote Ground
- (near TP16) PVIN = VIN = 10V - 14V
  7A(max)
- Load Step

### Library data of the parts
C1-C5 C44-C47 = CMP-0093169-1: 150µF Molded Tantalum Polymer Capacitor 20V 2917 (7343 Metric) 50mOhm @ 100kHz; Manufacturer: Kemet; IRMS_A: 2.1A; Leakage Current: 300uA; Dissipation Factor: 10%; SizeZ_mm: 3.1mm; AEC Qualified: No; Esr: 50m; Tolerance_%: 20%; Standoff Height: 0mm; Life: 2000Hours
C6-C8 = CMP-0009175-2: CAP, CERM, 10 uF, 25 V, +/- 10%, X7R, AEC-Q200 Grade 1, 1210; Manufacturer: MuRata; TaMin_C: -55°C; Polarized: N; SizeAreaWB_mm2: 14.7; Value1: Unknown; U/M: EA; Value: 10uF; TaMax_C: 125°C; SizeZ_mm: 2.8; SizeX_mm: 3.2; SizeY_mm: 2.5; Cap_Case: 1210; SizeArea_mm2: 8; AEC Qualified: Y; Cap_F: 10µF; AEC Grade: 1; AEC Category: Q200
C9-C16 C18 = CMP-0084679-1: CAP, CERM, 0.1 µF, 25 V,+/- 10%, X7R, AEC-Q200 Grade 1, 0603; Manufacturer: MuRata; TaMin_C: -55°C; SizeY_mm: 0.8; Polarized: N; SizeArea_mm2: 1.28; SizeZ_mm: 1; SizeX_mm: 1.6; AEC Qualified: Y; AEC Category: Q200; Value: 0.1uF; ValueDisplayed: 0.1µF; TaMax_C: 125°C; U/M: EA; SizeAreaWB_mm2: 4.68
C17 C19 C28 C29 C43 C62-C67 = CMP-0079630-1: CAP, CERM, 1 µF, 16 V,+/- 10%, X7R, AEC-Q200 Grade 1, 0805; Manufacturer: Kemet; TaMin_C: -55°C; Polarized: N; SizeAreaWB_mm2: 6.75; U/M: EA; Value: 1uF; TaMax_C: 125°C; SizeZ_mm: 1.45; SizeX_mm: 2; SizeY_mm: 1.25; Cap_Case: 0805; SizeArea_mm2: 2.5; AEC Qualified: Y; AEC Grade: 1; AEC Category: Q200
C20 = CMP-0006880-4: CAP, CERM, 150 pF, 50 V, +/- 5%, C0G/NP0, 0603; Manufacturer: Kemet; TaMin_C: -55°C; Polarized: N; SizeAreaWB_mm2: 4.68; Value1: Unknown; U/M: EA; Value: 150pF; TaMax_C: 125°C; SizeZ_mm: 1; SizeX_mm: 1.6; SizeY_mm: 0.8; SizeArea_mm2: 1.28; AEC Category: Q200
C21 = CMP-0007275-4: CAP, CERM, 56 pF, 100 V, +/- 5%, C0G/NP0, 0603; Manufacturer: MuRata; TaMin_C: -55°C; Polarized: N; SizeAreaWB_mm2: 4.68; Value1: Unknown; U/M: EA; Value: 56pF; TaMax_C: 125°C; SizeZ_mm: 1; SizeX_mm: 1.6; SizeY_mm: 0.8; SizeArea_mm2: 1.28; AEC Category: Q200
C22 = CMP-0006901-4: CAP, CERM, 0.022 uF, 50 V, +/- 10%, X7R, 0603; Manufacturer: Kemet; TaMin_C: -55°C; Polarized: N; Value1: Unknown; U/M: EA; TaMax_C: 125°C; SizeAreaWB_mm2: 4.68; SizeZ_mm: 1; SizeX_mm: 1.6; SizeY_mm: 0.8; SizeArea_mm2: 1.28; AEC Category: Q200
C23 = CMP-0007142-4: CAP, CERM, 0.47 uF, 25 V, +/- 10%, X7R, AEC-Q200 Grade 1, 0603; Manufacturer: MuRata; TaMin_C: -55°C; Polarized: N; SizeAreaWB_mm2: 4.68; Value1: Unknown; U/M: EA; Value: 0.47uF; TaMax_C: 125°C; SizeZ_mm: 1; SizeX_mm: 1.6; SizeY_mm: 0.8; SizeArea_mm2: 1.28; AEC Qualified: Y; AEC Category: Q200
C24 = CMP-0007460-5: CAP CER 0.056UF 50V X7R 0603; Manufacturer: Kyocera AVX; Polarized: N
C25 = CMP-0080734-1: CAP, CERM, 470 pF, 10 V,+/- 5%, C0G/NP0, 0603; Manufacturer: Wurth Elektronik; SizeAreaWB_mm2: 4.68; SizeArea_mm2: 1.28; AEC Qualified: N; AEC Category: Q200; Value: 470pF; TaMax_C: 125°C; SizeZ_mm: 1; TaMin_C: -55°C; SizeY_mm: 0.8; U/M: EA; SizeX_mm: 1.6
C26 C27 C31 = CMP-0085980-1: CAP, CERM, 1 µF, 35 V,+/- 10%, X7R, 0805; Manufacturer: MuRata; AEC Category: Q200; SizeZ_mm: 1.45; U/M: EA; Cap_Case: 0805; Polarized: N; Value: 1uF; TaMin_C: -55°C; TaMax_C: 125°C; SizeArea_mm2: 2.5; SizeX_mm: 2; SizeY_mm: 1.25; SizeAreaWB_mm2: 6.75
C30 = CMP-0079095-1: CAP, CERM, 0.1 µF, 50 V,+/- 10%, X7R, AEC-Q200 Grade 1, 0603; Manufacturer: AVX; SizeAreaWB_mm2: 4.68; SizeArea_mm2: 1.28; AEC Qualified: Y; AEC Category: Q200; Value: 0.1uF; TaMax_C: 125°C; SizeZ_mm: 1; Polarized: N; TaMin_C: -55°C; SizeY_mm: 0.8; U/M: EA; SizeX_mm: 1.6; ValueDisplayed: 0.1µF
C32-C41 = CMP-0122762-1: Cap Tant Polymer 1500uF 2.5V X CASE 20% (7.3 X 4.3 X 4mm) SMD 7343-43, X 15 mOhm 105°C T/R; Manufacturer: KEMET; AEC Qualified: No; IRMS_A: 4.1A; SizeZ_mm: 4.3mm; Dissipation Factor: 10%; Esr: 15m; Leakage Current: 375uA; Life: 2000Hours; Standoff Height: 0mm; Value: 1.5mF
C42 = CMP-0006979-5: CAP, CERM, 0.1 uF, 25 V, +/- 10%, X7R, 0603; Manufacturer: Kemet; TaMin_C: -55°C; Polarized: N; SizeAreaWB_mm2: 4.68; Value1: Unknown; U/M: EA; Value: 0.1uF; TaMax_C: 125°C; SizeZ_mm: 1; SizeX_mm: 1.6; SizeY_mm: 0.8; SizeArea_mm2: 1.28; AEC Category: Q200
C48-C50 = CMP-0081783-1: CAP, CERM, 22 µF, 16 V,+/- 10%, X7R, 1210; Manufacturer: Samsung; TaMin_C: -55°C; Polarized: N; SizeAreaWB_mm2: 14.7; U/M: EA; Value: 22uF; TaMax_C: 125°C; SizeZ_mm: 2.7; SizeX_mm: 3.2; SizeY_mm: 2.5; Cap_Case: 1210; SizeArea_mm2: 8; AEC Category: Q200
C51-C54 = CMP-0008687-2: CAP, CERM, 10 uF, 10 V, +/- 10%, X7R, 1206; Manufacturer: TDK; TaMin_C: -55°C; ESR_ohm: 2.454m; Polarized: N; SizeAreaWB_mm2: 10.92; Value1: 0.002454 ohm; U/M: EA; Value: 10uF; TaMax_C: 125°C; SizeZ_mm: 1.35; SizeX_mm: 3.2; SizeY_mm: 1.6; SizeArea_mm2: 5.12; Cap_F: 10µF; IRMS_A: 4.6318A; AEC Category: Q200
C55-C58 = CMP-0007690-2: CAP, CERM, 4.7 uF, 10 V, +/- 10%, X7R, 0805; Manufacturer: Wurth Elektronik; TaMin_C: -55°C; Polarized: N; SizeAreaWB_mm2: 6.75; Value1: Unknown; U/M: EA; Value: 4.7uF; TaMax_C: 125°C; SizeZ_mm: 1.45; SizeX_mm: 2; SizeY_mm: 1.25; Cap_Case: 0805; SizeArea_mm2: 2.5; AEC Category: Q200
C59-C61 = CMP-0008317-2: CAP, CERM, 2.2 uF, 10 V, +/- 10%, X7R, 0805; Manufacturer: MuRata; TaMin_C: -55°C; ESR_ohm: 6m; Polarized: N; SizeAreaWB_mm2: 6.75; Value1: 0.006 ohm; U/M: EA; Value: 2.2uF; TaMax_C: 125°C; SizeZ_mm: 1.45; SizeX_mm: 2; SizeY_mm: 1.25; Cap_Case: 0805; SizeArea_mm2: 2.5; AEC Category: Q200
C68-C73 = CMP-0006946-4: CAP, CERM, 0.47 uF, 10 V, +/- 10%, X7R, 0603; Manufacturer: Kemet; TaMin_C: -55°C; Polarized: N; SizeAreaWB_mm2: 4.68; Value1: Unknown; U/M: EA; Value: 0.47uF; TaMax_C: 125°C; SizeZ_mm: 1; SizeX_mm: 1.6; SizeY_mm: 0.8; SizeArea_mm2: 1.28; AEC Category: Q200
C74-C79 = CMP-0064931-4: CAP, CERM, 0.1 uF, 10 V,+/- 10%, X7R, 0603; Manufacturer: Wurth Elektronik; TaMin_C: -55°C; Polarized: N; SizeAreaWB_mm2: 4.68; Value1: Unknown; U/M: EA; Value: 0.1uF; TaMax_C: 125°C; SizeZ_mm: 1; SizeX_mm: 1.6; SizeY_mm: 0.8; SizeArea_mm2: 1.28; AEC Category: Q200
D1 = CMP-0076963-2: Diode, Superfast Rectifier, 50 V, 3 A, SMB; Manufacturer: Diodes Inc.; Value1: 3A; Green_REACh: Incomplete; SizeY_mm: 3.81; AEC Category: Q101; TJmax_C: 150°C; SizeAreaWB_mm2: 44.156; SizeX_mm: 5.6; SizeArea_mm2: 21.336; Value2: 0.9V; Vr_V: 50V; Green_Lifecycle: Not Set; SizeZ_mm: 2.6; Vf_V: 900mV; Value: 50V; RJC_CperW: 10.0
D2 = CMP-0124121-1: Diode Zener Single 13V 500mW 2-Pin SOD-123 T/R; Manufacturer: Vishay; AEC Qualified: No; SizeZ_mm: 1.35mm; TJmax_C: 150°C; Vr_V: 10V; Max Reverse Leakage Current: 0.1uA; Power_W: 300mW; Zener Impedance: 25Ω
D3 = CMP-0122761-1: Rectifier Diode Schottky 200V 5A Automotive AEC-Q101 2-Pin SMA T/R; Manufacturer: Good-Ark; AEC Qualified: Yes; SizeZ_mm: 2.25mm; TJmax_C: 150°C; AEC Grade: Grade 0; Cap_F: 96pF; Max Surge Forward Current: 120A; Peak Reverse Current: 30uA; Standoff Height: 0mm
J1 J6 J7 = CMP-0055433-1: Compact Probe Tip Circuit Board Test Points, TH, 25 per; Manufacturer: Tektronix; PartNumber: 131-5031-00; CNHeader: FALSE; Green_Lifecycle: Not Set; Green_REACh: Incomplete
J2 = CMP-0078537-1: Fixed Terminal Blocks MKDSP 10 HV/ 2-10; Manufacturer: Phoenix Contact; Current_A: 76A; Voltage_V: 1kV; Symbol Name: SYM-1929517; Row_Count: 1
J3 = CMP-0098472-1: SMA Connector Jack, Female Socket 50Ohm Surface Mount Solder; Manufacturer: Wurth Electronics; ContactFinish: Gold,Nickel; Shrouded: true; AEC Qualified: No; Conn Orientation: Straight; Dielectric Material: PTFE; Frequency_Fixed: 0-18GHz; Impedance: 50Ω; Is Female: yes; SizeZ_mm: 9.04mm
J4 = CMP-0055393-3: Standard Banana Jack, insulated, 10A, red; Manufacturer: DEM Manufacturing; Green_REACh: Incomplete; Green_Lifecycle: Not Set
J5 = CMP-0055389-3: Standard Banana Jack, insulated, 10A, black; Manufacturer: DEM Manufacturing; Green_REACh: Incomplete; Green_Lifecycle: Not Set
L1 = CMP-0060952-1: Inductor, Shielded, Composite, 680 nH, 36 A, 0.00087 ohm, SMD; Manufacturer: Coilcraft; Isat: 62A @ 30% inductance drop; Irms: 36A @ 20C rise; Green_Lifecycle: Not Set; SizeAreaWB_mm2: 159.6; DCR_ohm: 870µ; Green_REACh: Incomplete; Value: 680nH; Imax_A: 36A; SizeZ_mm: 10; SizeX_mm: 11.3; SizeArea_mm2: 113; AEC Qualified: N; AEC Category: Q200
Q1-Q4 = CMP-0044865-1: MOSFET N-Channel 40 V 80A (Tc) Surface Mount 5-SMD; Manufacturer: EPC Space; AEC Qualified: No; QgTyp_nC: 22nC @ 0V; Rdson45_ohm: 3.7m; SizeZ_mm: 2.235mm; VdsMax_V: 40V; Vgs_V: 6V; ChMode: False; Input Capacitace At Vds: 2830pF @ 20V; Number Of Channels: 1; Pulse Drain Current: 530A; Rthja Max: 48°C/W; Threshold Vgs Max: 2.5V; Threshold Vgs Min: 0.8V; TJmax_C: +150°C
Q5 = CMP-0000264-1: MOSFET, N-CH, 25 V, 113 A, DQH0008A (VSON-CLIP-8); Alternate Manufacturer: None; Manufacturer: Texas Instruments; SizeZ_mm: 1.05; ChType: N; Value2: 6.7 nC; Value1: 0.005; VdsMax_V: 25V; SizeX_mm: 6; SizeY_mm: 5; Vgs_V: 16V; Value: 25V; Rdson45_ohm: 5.4m; SizeArea_mm2: 30; AEC Category: Q101; IdsMax_A: 113A; SizeAreaWB_mm2: 56; U/M: EA; QgTyp_nC: 6.7
R1 = CMP-0023387-3: RES, 50, 0.1%, 0.125 W, 0603; Manufacturer: Vishay Thin Film; Power_W: 125mW; TempCo: 25 ppm/C; Value_Code: 50R0; U/M: EA; Value: 50; SizeX_mm: 1.6; SizeY_mm: 0.8; SizeZ_mm: 1; Value2: 0.125W; SizeArea_mm2: 1.28; AEC Qualified: N; VDC_V: 50V; AEC Category: Q200
R2 R22 R35 R37 = CMP-0023392-3: RES, 10.0 k, 0.1%, 0.0375 W, 0603; Manufacturer: Vishay Sfernice; Power_W: 37.5mW; TempCo: 15 ppm/C; Value_Code: 10k0; U/M: EA; Value: 10.0k; EIA_Code: E192; Res_ohm: 10k; SizeX_mm: 1.6; SizeY_mm: 0.8; SizeZ_mm: 1; SizeArea_mm2: 1.28; VDC_V: 75V; AEC Category: Q200
R3 = CMP-0022138-4: RES, 1.00 M, 1%, 0.1 W, AEC-Q200 Grade 0, 0603; Manufacturer: Vishay-Dale; Power_W: 100mW; TempCo: 100 ppm/C; Value_Code: 1M00; Value: 1.00Meg; EIA_Code: E96; Res_ohm: 1M; SizeX_mm: 1.6; SizeY_mm: 0.8; SizeZ_mm: 1; Value2: 0.1W; SizeArea_mm2: 1.28; AEC Qualified: Y; VDC_V: 75V; AEC Category: Q200; AEC Grade: 0
R4 = CMP-0023520-3: RES, 33.0 k, 0.1%, 0.1 W, 0603; Manufacturer: Susumu Co Ltd; Power_W: 100mW; TempCo: 25 ppm/C; Value_Code: 33k0; U/M: EA; Value: 33.0k; Res_ohm: 33k; SizeX_mm: 1.6; SizeY_mm: 0.8; SizeZ_mm: 1; Value2: 0.1W; SizeArea_mm2: 1.28; VDC_V: 75V; AEC Category: Q200
R5 R8 R10 R16-R19 R21 R28-R30 R32-R34 R36 = CMP-0081973-1: RES, 0, 0%, 0.25 W, AEC-Q200 Grade 0, 0603; Manufacturer: Vishay-Dale; SizeAreaWB_mm2: 4.68; SizeArea_mm2: 1.28; AEC Qualified: Y; AEC Category: Q200; Value: 0; SizeZ_mm: 1; SizeY_mm: 0.8; Power_W: 250mW; Value2: 0.25W; SizeX_mm: 1.6
R6 = CMP-0025687-2: RES, 10.0, 0.1%, 0.1 W, 0603; Manufacturer: Vishay-Dale; Power_W: 100mW; TempCo: 25 ppm/C; Value_Code: 10R0; U/M: EA; Value: 10.0; EIA_Code: E192; Res_ohm: 10; SizeX_mm: 1.6; SizeY_mm: 0.8; SizeZ_mm: 1; Value2: 0.1W; SizeArea_mm2: 1.28; VDC_V: 75V; AEC Category: Q200
R7 = CMP-0024214-3: RES, 40.2 k, 0.1%, 0.1 W, 0603; Manufacturer: Yageo America; Power_W: 100mW; TempCo: 25 ppm/C; Value_Code: 40k2; U/M: EA; Value: 40.2k; EIA_Code: E192; SizeX_mm: 1.6; SizeY_mm: 0.8; SizeZ_mm: 1; Value2: 0.1W; SizeArea_mm2: 1.28; VDC_V: 75V; AEC Category: Q200
R9 = CMP-0023416-3: RES, 110 k, 0.1%, 0.1 W, 0603; Manufacturer: Susumu Co Ltd; Power_W: 100mW; TempCo: 25 ppm/C; U/M: EA; Value: 110k; EIA_Code: E192; SizeX_mm: 1.6; SizeY_mm: 0.8; SizeZ_mm: 1; Value2: 0.1W; SizeArea_mm2: 1.28; VDC_V: 75V; AEC Category: Q200
R11 R12 R14 = CMP-0024180-2: RES 397K OHM 1% 1/10W 060; Manufacturer: KOA Speer Electronics, Inc.
R13 = CMP-0024283-3: RES, 49.9 k, 0.1%, 0.1 W, 0603; Manufacturer: Yageo America; Power_W: 100mW; TempCo: 25 ppm/C; Value_Code: 49k9; U/M: EA; Value: 49.9k; EIA_Code: E192; SizeX_mm: 1.6; SizeY_mm: 0.8; SizeZ_mm: 1; Value2: 0.1W; SizeArea_mm2: 1.28; VDC_V: 75V; AEC Category: Q200
R15 = CMP-0022711-2: RES, 2.20, 1%, 0.1 W, 0603; Manufacturer: Panasonic; Power_W: 100mW; TempCo: 200 ppm/C; Value_Code: 2R20; U/M: EA; Value: 2.20; Res_ohm: 2.2; SizeX_mm: 1.6; SizeY_mm: 0.8; SizeZ_mm: 1; Value2: 0.1W; SizeArea_mm2: 1.28; AEC Category: Q200
R20 = CMP-0025805-4: RES, 3.3, 5%, 0.1 W, AEC-Q200 Grade 0, 0603; Manufacturer: Vishay-Dale; Power_W: 100mW; TempCo: 200 ppm/C; Value_Code: 3R30; Value: 3.3; EIA_Code: E24; SizeX_mm: 1.6; SizeY_mm: 0.8; SizeZ_mm: 1; Value2: 0.1W; SizeArea_mm2: 1.28; AEC Qualified: Y; VDC_V: 75V; AEC Category: Q200; AEC Grade: 0
R23 R25 R27 = CMP-0015108-2: RES, 0.007, 1%, 3 W, 2512 WIDE; Manufacturer: Susumu Co Ltd; Power_W: 3W; TempCo: 50 ppm/C; SizeAreaWB_mm2: 43.16; Value_Code: 7L000; U/M: EA; Value: 0.007; EIA_Code: E96; Res_ohm: 7m; SizeX_mm: 3.2; SizeY_mm: 6.3; SizeZ_mm: 0.7; SizeArea_mm2: 20.16; AEC Category: Q200
R24 = CMP-0024147-3: RES, 35.7 k, 0.1%, 0.1 W, 0603; Manufacturer: Yageo America; Power_W: 100mW; TempCo: 25 ppm/C; Value_Code: 35k7; U/M: EA; Value: 35.7k; EIA_Code: E192; SizeX_mm: 1.6; SizeY_mm: 0.8; SizeZ_mm: 1; Value2: 0.1W; SizeArea_mm2: 1.28; VDC_V: 75V; AEC Category: Q200
R26 = CMP-0024164-3: RES, 37.4 k, 0.1%, 0.1 W, 0603; Manufacturer: Yageo America; Power_W: 100mW; TempCo: 25 ppm/C; Value_Code: 37k4; U/M: EA; Value: 37.4k; EIA_Code: E192; SizeX_mm: 1.6; SizeY_mm: 0.8; SizeZ_mm: 1; Value2: 0.1W; SizeArea_mm2: 1.28; VDC_V: 75V; AEC Category: Q200
R31 = CMP-0023466-3: RES, 2.10 k, 0.1%, 0.1 W, 0603; Manufacturer: Susumu Co Ltd; Power_W: 100mW; TempCo: 25 ppm/C; Value_Code: 2k10; U/M: EA; Value: 2.10k; EIA_Code: E192; Res_ohm: 2.1k; SizeX_mm: 1.6; SizeY_mm: 0.8; SizeZ_mm: 1; Value2: 0.1W; SizeArea_mm2: 1.28; VDC_V: 75V; AEC Category: Q200
R38 = CMP-0015409-2: RES 0.062 OHM 1% 2W 2512; Manufacturer: Yageo; Value: 0.062
TP1-TP5 TP8 TP9 TP18 = CMP-0055149-2: Test Point, Multipurpose, White, TH; Manufacturer: Keystone Electronics; ContactFinish: Silver; CT: TRUE; CNHeader: FALSE; Green_Lifecycle: Active; Green_REACh: Passed
TP6 TP7 TP16 = CMP-0055147-2: Test Point, Multipurpose, Red, TH; Manufacturer: Keystone Electronics; CT: TRUE; ContactFinish: Silver; Green_Lifecycle: Active; CNHeader: FALSE; Green_REACh: Passed
TP10-TP15 = CMP-0055148-2: Test Point, Multipurpose, Black, TH; Manufacturer: Keystone Electronics; CNHeader: FALSE; ContactFinish: Silver; Green_REACh: Passed; Green_Lifecycle: Active; CT: TRUE
TP17 = CMP-0055148-2: Test Point, Multipurpose, Black, TH; Manufacturer: Keystone Electronics; CNHeader: FALSE; Green_Lifecycle: Active; Green_REACh: Passed; ContactFinish: Silver; CT: TRUE
U1 = CMP-0094375-1: Radiation-Hardened 2 MHz Current Mode PWM Controllers in Space Enhanced Plastic; Manufacturer: Texas Instruments; Part Number: TPS7H5006MPWSEP; Min Supply Voltage: 4V; Standoff Height: 0.05mm; Output Type: AdjustableProgrammable; Max Supply Voltage: 14V; SizeZ_mm: 1.2mm; TJmax_C: +125°C; Switching Frequency: 100-2000MHz; Switching Topology: Buck,Flyback,Push-Pull,Other; AEC Qualified: No; Nominal Supply Current: 6.25-14mA; Max Duty Cycle: 100%; Number Of Outputs: 1
U2 = CMP-0120202-4: TPS7H6025MDCATSEP; Manufacturer: Texas Instruments; SizeZ_mm: 1.2mm; Standoff Height: 0.05mm; CompType: IC

## Sheet TIDA-050088_Sequencing.SchDoc
size 558 x 431 mm; Date: Not shown in title block; ApprovedBy: Not shown in title block; CheckedBy: Not shown in title block; Author: Not shown in title block; CompanyName: Not shown in title block; Engineer: Not shown in title block; Organization: Not shown in title block; Address1: Not shown in title block; Address2: Not shown in title block; Address3: Not shown in title block; Address4: Not shown in title block; DocumentNumber: 2; Revision: Use project parameter SCH_Rev; SheetNumber: 3; SheetTotal: 7; PageSetup: Record=PageOptions¦CenterHorizontal=True¦CenterVertical=True¦PrintScale=1.00¦XCorrection=1.00¦YCorrection=1.00¦PrintKind=0¦BorderSize=5000000¦LeftOffset=0¦BottomOffset=0¦Orientation=2¦PaperLength=1000¦PaperWidth=1000¦Scale=100¦PaperSource=15¦PrintQuality=600¦MediaType=1¦DitherType=10¦PaperKind=Letter¦PrintScaleMode=1
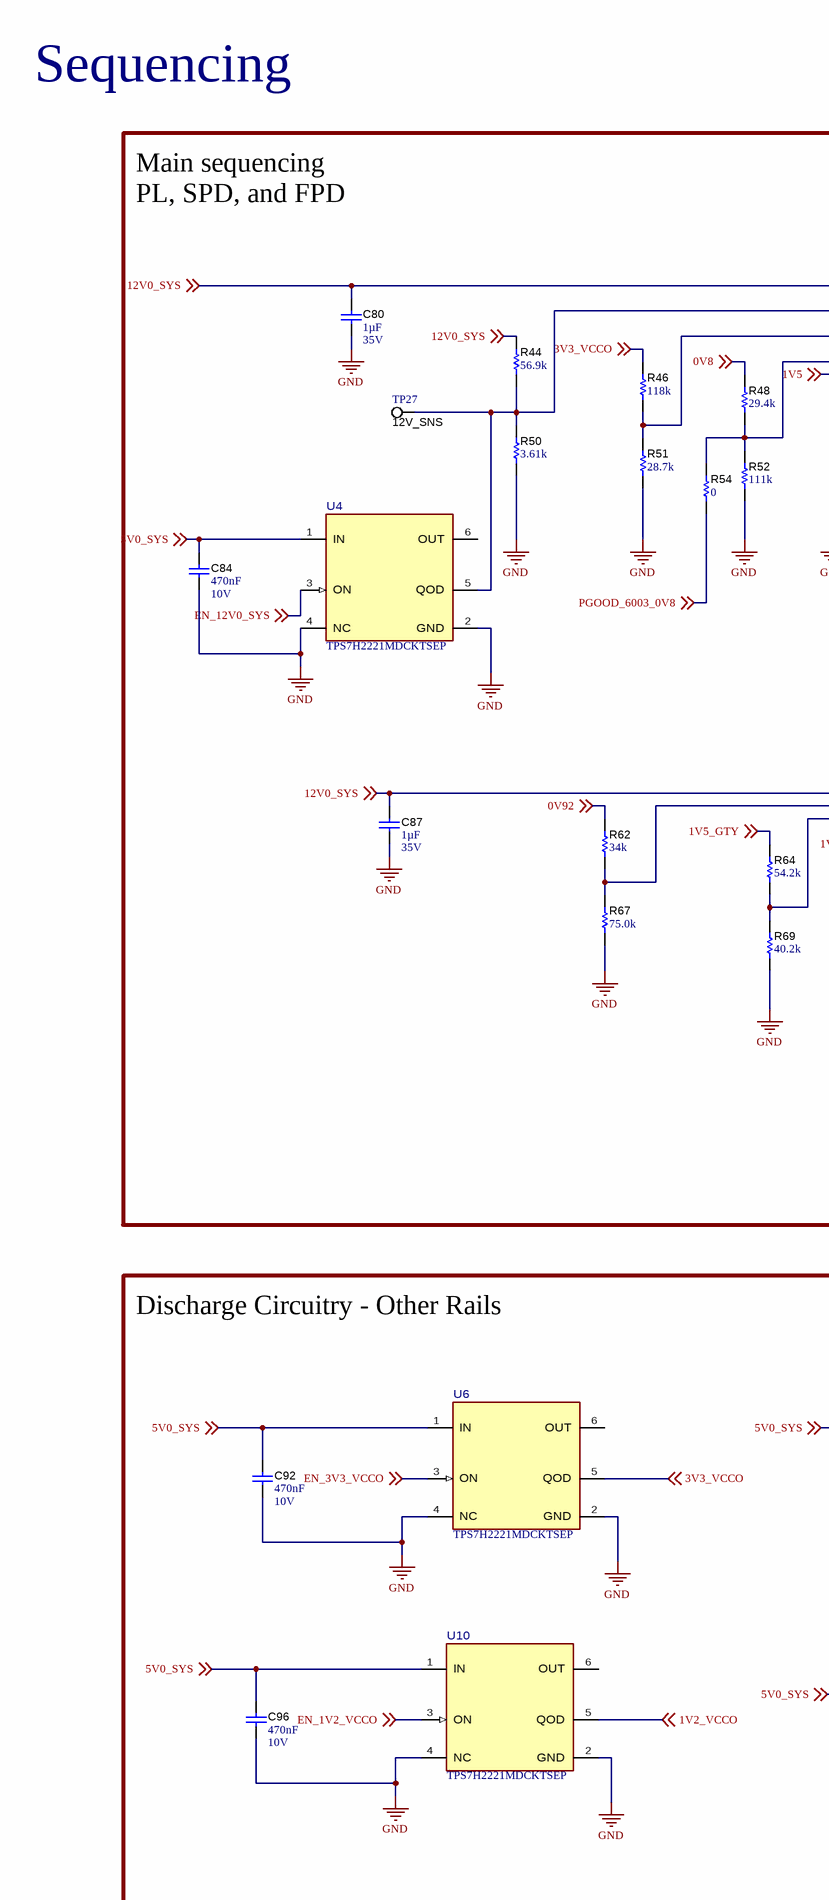
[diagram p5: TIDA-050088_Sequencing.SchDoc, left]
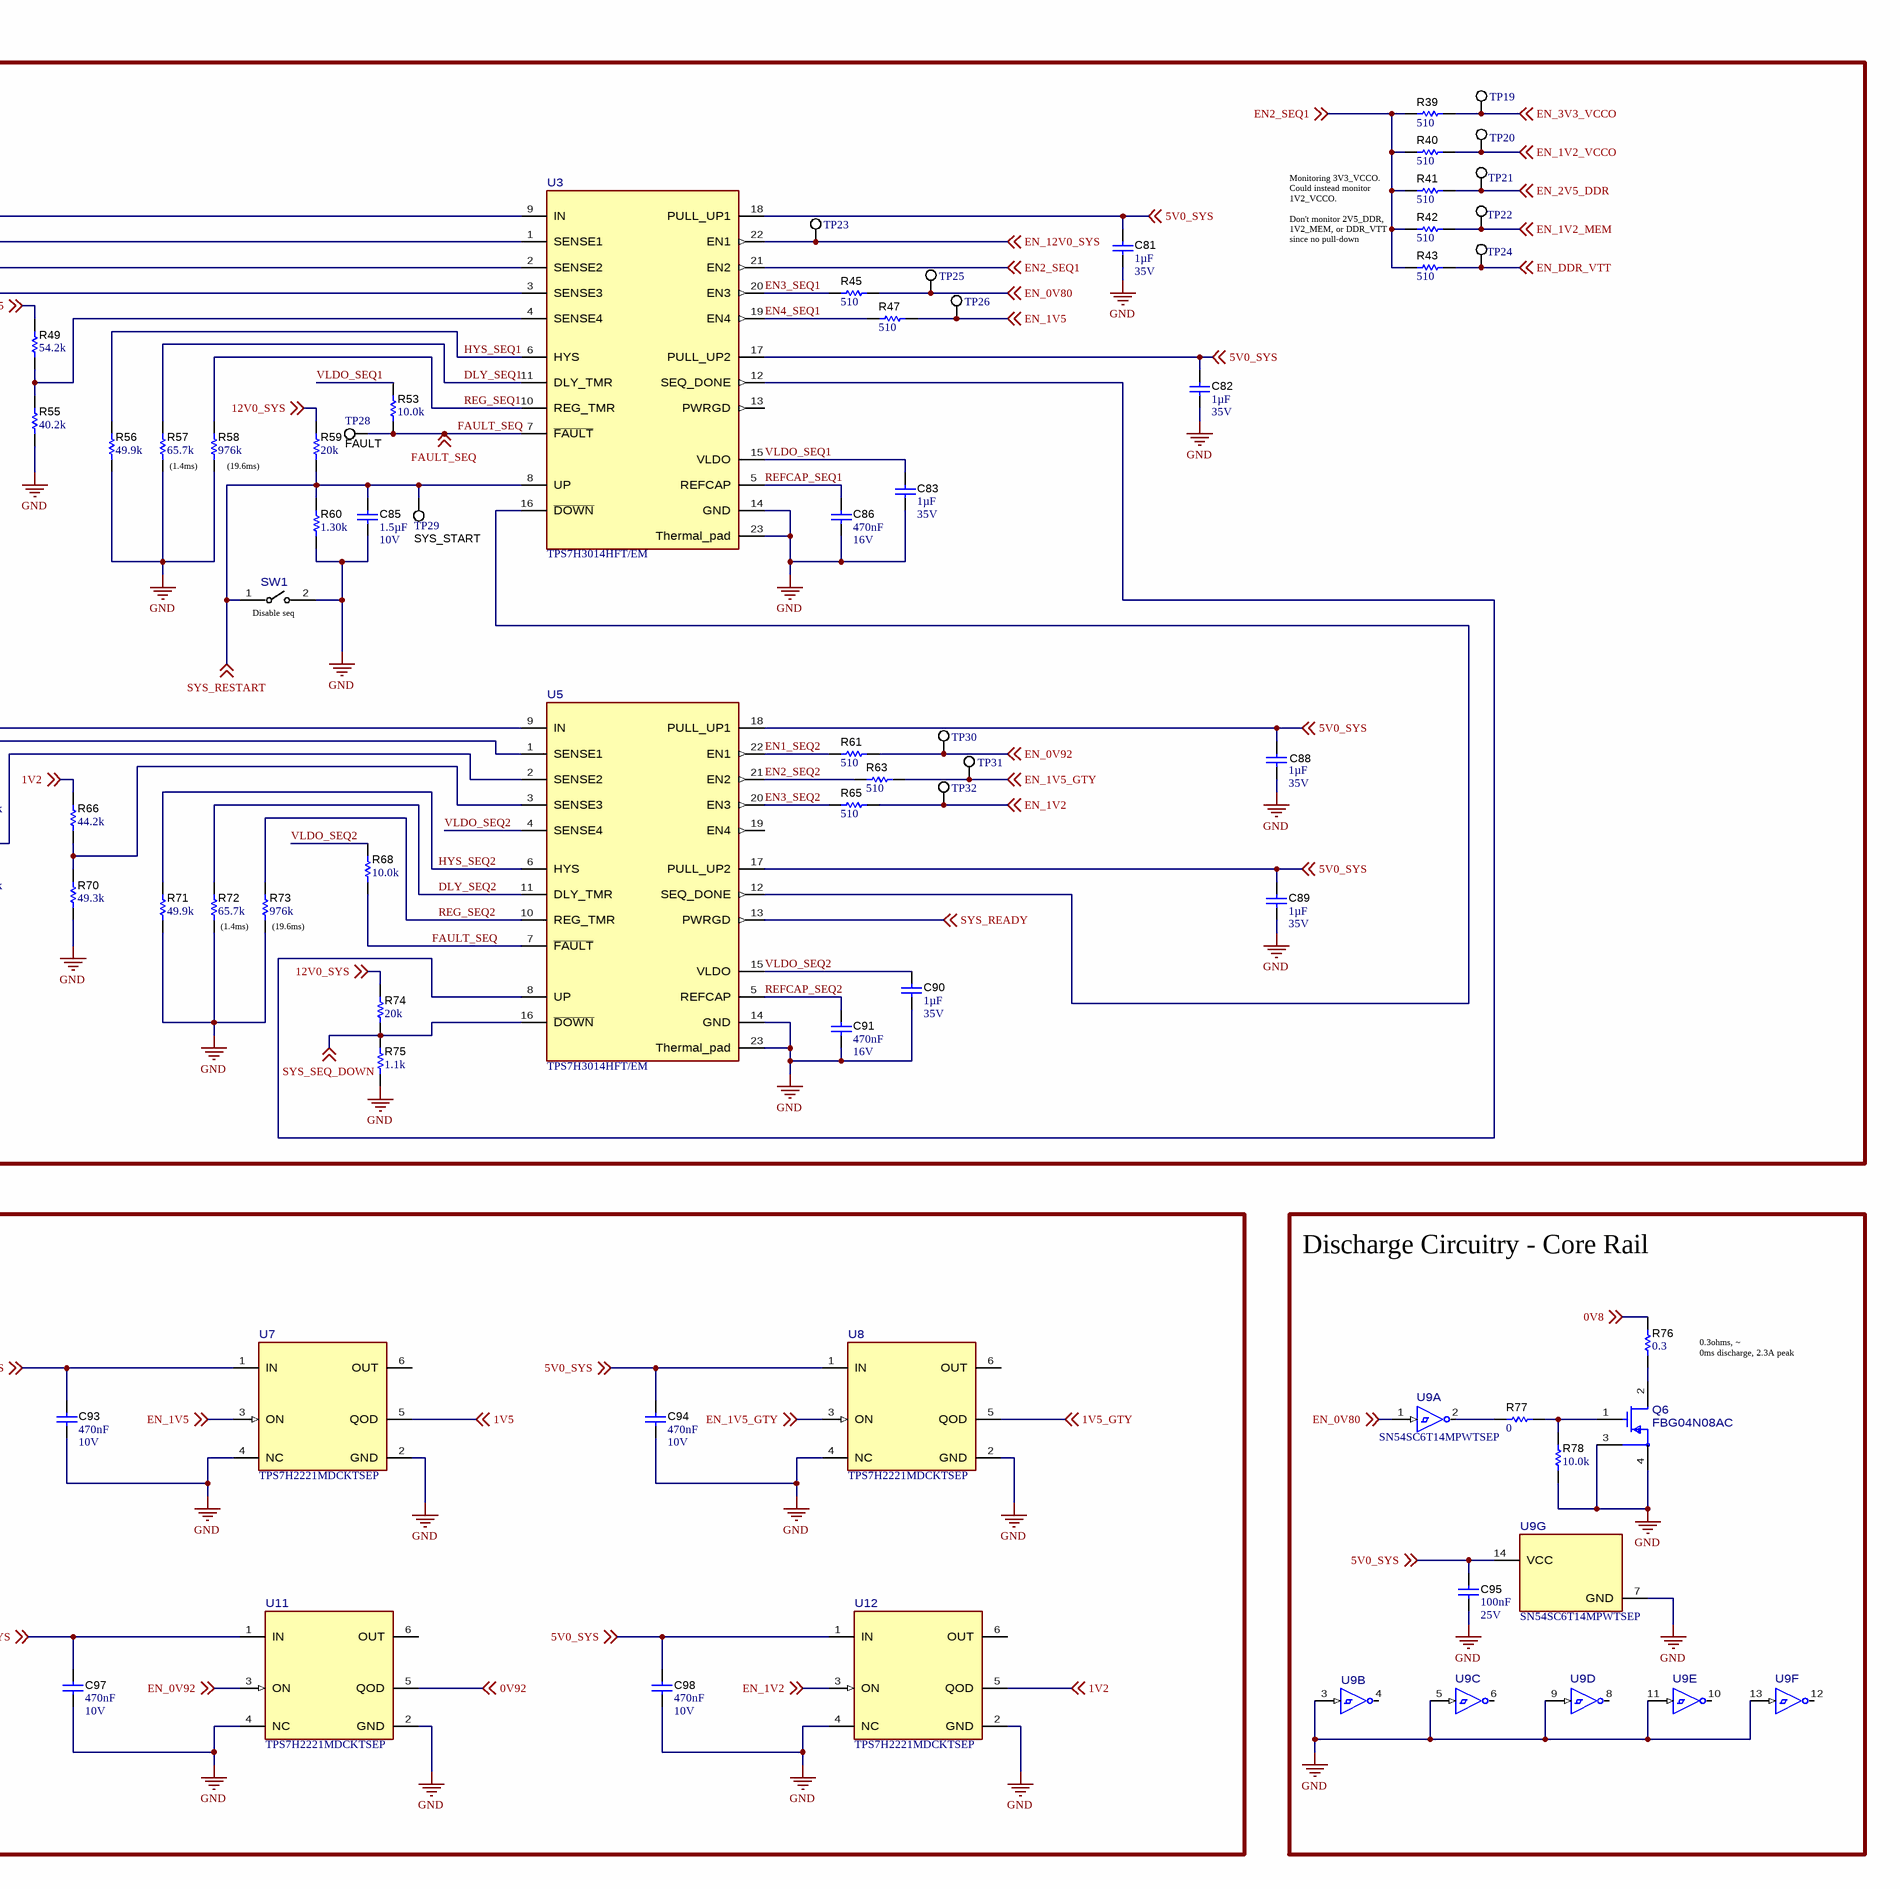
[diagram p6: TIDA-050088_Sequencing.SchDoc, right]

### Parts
C80  Cap_F: 1µF  VDC_V: 35V  [0805_HV]  (hidden comment: GRM219R7YA105KA12D)
C81  Cap_F: 1µF  VDC_V: 35V  [0805_HV]  (hidden comment: GRM219R7YA105KA12D)
C82  Cap_F: 1µF  VDC_V: 35V  [0805_HV]  (hidden comment: GRM219R7YA105KA12D)
C83  Cap_F: 1µF  VDC_V: 35V  [0805_HV]  (hidden comment: GRM219R7YA105KA12D)
C84  Cap_F: 470nF  VDC_V: 10V  [0603]  (hidden comment: C0603C474K8RACTU)
C85  Cap_F: 1.5µF  VDC_V: 10V  [0805_HV]  (hidden comment: C0805C155K8RACTU)
C86  Cap_F: 470nF  VDC_V: 16V  [0805_HV]  (hidden comment: 0805YC474JAT2A)
C87  Cap_F: 1µF  VDC_V: 35V  [0805_HV]  (hidden comment: GRM219R7YA105KA12D)
C88  Cap_F: 1µF  VDC_V: 35V  [0805_HV]  (hidden comment: GRM219R7YA105KA12D)
C89  Cap_F: 1µF  VDC_V: 35V  [0805_HV]  (hidden comment: GRM219R7YA105KA12D)
C90  Cap_F: 1µF  VDC_V: 35V  [0805_HV]  (hidden comment: GRM219R7YA105KA12D)
C91  Cap_F: 470nF  VDC_V: 16V  [0805_HV]  (hidden comment: 0805YC474JAT2A)
C92  Cap_F: 470nF  VDC_V: 10V  [0603]  (hidden comment: C0603C474K8RACTU)
C93  Cap_F: 470nF  VDC_V: 10V  [0603]  (hidden comment: C0603C474K8RACTU)
C94  Cap_F: 470nF  VDC_V: 10V  [0603]  (hidden comment: C0603C474K8RACTU)
C95  Cap_F: 100nF  VDC_V: 25V  [0603]  (hidden comment: C0603X104K3RACTU)
C96  Cap_F: 470nF  VDC_V: 10V  [0603]  (hidden comment: C0603C474K8RACTU)
C97  Cap_F: 470nF  VDC_V: 10V  [0603]  (hidden comment: C0603C474K8RACTU)
C98  Cap_F: 470nF  VDC_V: 10V  [0603]  (hidden comment: C0603C474K8RACTU)
Q6  FBG04N08AC  [FP-FBG04N08ACH_FSMD-A-MFG]
R39  ValueDisplayed: 510  [0603]  (hidden comment: CRCW0603510RJNEA)
R40  ValueDisplayed: 510  [0603]  (hidden comment: CRCW0603510RJNEA)
R41  ValueDisplayed: 510  [0603]  (hidden comment: CRCW0603510RJNEA)
R42  ValueDisplayed: 510  [0603]  (hidden comment: CRCW0603510RJNEA)
R43  ValueDisplayed: 510  [0603]  (hidden comment: CRCW0603510RJNEA)
R44  ValueDisplayed: 56.9k  [0603]  (hidden comment: RT0603DRE0756K9L)
R45  ValueDisplayed: 510  [0603]  (hidden comment: CRCW0603510RJNEA)
R46  ValueDisplayed: 118k  [0603]  (hidden comment: RT0603BRD07118KL)
R47  ValueDisplayed: 510  [0603]  (hidden comment: CRCW0603510RJNEA)
R48  ValueDisplayed: 29.4k  [0603]  (hidden comment: RT0603BRD0729K4L)
R49  ValueDisplayed: 54.2k  [0603]  (hidden comment: TNPW060354K2BEEN)
R50  ValueDisplayed: 3.61k  [0603]  (hidden comment: RT0603BRD073K61L)
R51  ValueDisplayed: 28.7k  [0603]  (hidden comment: RT0603BRD0728K7L)
R52  ValueDisplayed: 111k  [0603]  (hidden comment: RN73H1JTTD1113B25)
R53  ValueDisplayed: 10.0k  [0603]  (hidden comment: PHT0603Y1002BGT200)
R54  ValueDisplayed: 0  [0603]  (hidden comment: RCS06030000Z0EA)
R55  ValueDisplayed: 40.2k  [0603]  (hidden comment: RT0603BRD0740K2L)
R56  ValueDisplayed: 49.9k  [0603]  (hidden comment: RG1608P-4992-B-T5)
R57  ValueDisplayed: 65.7k  [0603]  (hidden comment: RT0603DRE0765K7L)
R58  ValueDisplayed: 976k  [0603]  (hidden comment: RC0603FR-07976KL)
R59  ValueDisplayed: 20k  [0603]  (hidden comment: ERA-3AEB203V)
R60  ValueDisplayed: 1.30k  [0603]  (hidden comment: RG1608P-132-B-T5)
R61  ValueDisplayed: 510  [0603]  (hidden comment: CRCW0603510RJNEA)
R62  ValueDisplayed: 34k  [0603]  (hidden comment: RN73H1JTTD3402B25)
R63  ValueDisplayed: 510  [0603]  (hidden comment: CRCW0603510RJNEA)
R64  ValueDisplayed: 54.2k  [0603]  (hidden comment: TNPW060354K2BEEN)
R65  ValueDisplayed: 510  [0603]  (hidden comment: CRCW0603510RJNEA)
R66  ValueDisplayed: 44.2k  [0603]  (hidden comment: RT0603BRD0744K2L)
R67  ValueDisplayed: 75.0k  [0603]  (hidden comment: RT0603BRD0775KL)
R68  ValueDisplayed: 10.0k  [0603]  (hidden comment: PHT0603Y1002BGT200)
R69  ValueDisplayed: 40.2k  [0603]  (hidden comment: RT0603BRD0740K2L)
R70  ValueDisplayed: 49.3k  [0603]  (hidden comment: RT0603BRD0749K3L)
R71  ValueDisplayed: 49.9k  [0603]  (hidden comment: RG1608P-4992-B-T5)
R72  ValueDisplayed: 65.7k  [0603]  (hidden comment: RT0603DRE0765K7L)
R73  ValueDisplayed: 976k  [0603]  (hidden comment: RC0603FR-07976KL)
R74  ValueDisplayed: 20k  [0603]  (hidden comment: ERA-3AEB203V)
R75  ValueDisplayed: 1.1k  [0603]  (hidden comment: ERA-3AEB112V)
R76  ValueDisplayed: 0.3  [2010]  (hidden comment: CSRN2010FKR300)
R77  ValueDisplayed: 0  [0603]  (hidden comment: RCS06030000Z0EA)
R78  ValueDisplayed: 10.0k  [0603]  (hidden comment: PHT0603Y1002BGT200)
SW1  A6TN-1104  [FP-A6TN-1104_PTH_SW_7MM50_4MM48-MFG]  (value not drawn)
TP19  EN_3V3_VCCO  [Keystone5012]  (value not drawn)
TP20  EN_1V2_VCCO  [Keystone5012]  (value not drawn)
TP21  EN_2V5_DDR  [Keystone5012]  (value not drawn)
TP22  EN_1V2_MEM  [Keystone5012]  (value not drawn)
TP23  EN_12V0_SYS  [Keystone5012]  (value not drawn)
TP24  EN_DDR_VTT  [Keystone5012]  (value not drawn)
TP25  EN__0V80  [Keystone5012]  (value not drawn)
TP26  EN_1V5  [Keystone5012]  (value not drawn)
TP27  12V_SNS  [Keystone5012]
TP28  FAULT  [Keystone5012]
TP29  SYS_START  [Keystone5012]
TP30  EN_0V92  [Keystone5012]  (value not drawn)
TP31  EN_1V5_GTY  [Keystone5012]  (value not drawn)
TP32  EN_1V2  [Keystone5012]  (value not drawn)
U3  TPS7H3014HFT/EM  [HFT0022A-C01-MFG]
U4  TPS7H2221MDCKTSEP  [DCK0006A-MFG]
U5  TPS7H3014HFT/EM  [HFT0022A-C01-MFG]
U6  TPS7H2221MDCKTSEP  [DCK0006A-MFG]
U7  TPS7H2221MDCKTSEP  [DCK0006A-MFG]
U8  TPS7H2221MDCKTSEP  [DCK0006A-MFG]
U9  SN54SC6T14MPWTSEP  [PW0014A-MFG]  (parts A,B,C,D,E,F,G of 7)
U10  TPS7H2221MDCKTSEP  [DCK0006A-MFG]
U11  TPS7H2221MDCKTSEP  [DCK0006A-MFG]
U12  TPS7H2221MDCKTSEP  [DCK0006A-MFG]

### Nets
GND: C80.2 C81.2 C82.2 C83.2 C84.2 C85.2 C86.2 C87.2 C88.2 C89.2 C90.1 C91.2 C92.2 C93.2 C94.2 C95.2 C96.2 C97.2 C98.2 Q6.3(SS) Q6.4(S) R50.1 R51.1 R52.1 R55.1 R56.1 R57.1 R58.1 R60.1 R67.1 R69.1 R70.1 R71.1 R72.1 R73.1 R75.1 R78.1 SW1.2 U3.14(GND) U3.23(Thermal_pad) U4.2(GND) U4.4(NC) U5.14(GND) U5.23(Thermal_pad) U6.2(GND) U6.4(NC) U7.2(GND) U7.4(NC) U8.2(GND) U8.4(NC) U9.3(2A) U9.5(3A) U9.7(GND) U9.9(4A) U9.11(5A) U9.13(6A) U10.2(GND) U10.4(NC) U11.2(GND) U11.4(NC) U12.2(GND) U12.4(NC)
0V8: R48.2 R76.2 ; off-sheet 0V8
0V92: R62.2 U11.5(QOD) ; off-sheet 0V92
1V2: R66.2 U12.5(QOD) ; off-sheet 1V2
1V2_VCCO: U10.5(QOD) ; off-sheet 1V2_VCCO
1V5: R49.2 U7.5(QOD) ; off-sheet 1V5
1V5_GTY: R64.2 U8.5(QOD) ; off-sheet 1V5_GTY
3V3_VCCO: R46.2 U6.5(QOD) ; off-sheet 3V3_VCCO
5V0_SYS: C81.1 C82.1 C84.1 C88.1 C89.1 C92.1 C93.1 C94.1 C95.1 C96.1 C97.1 C98.1 U3.17(PULL_UP2) U3.18(PULL_UP1) U4.1(IN) U5.17(PULL_UP2) U5.18(PULL_UP1) U6.1(IN) U7.1(IN) U8.1(IN) U9.14(VCC) U10.1(IN) U11.1(IN) U12.1(IN) ; off-sheet 5V0_SYS
12V0_SYS: C80.1 C87.1 R44.2 R59.2 R74.2 U3.9(IN) U5.9(IN) ; off-sheet 12V0_SYS
DLY_SEQ1: R57.2 U3.11(DLY_TMR)
DLY_SEQ2: R72.2 U5.11(DLY_TMR)
EN1_SEQ2: R61.1 U5.22(EN1)
EN2_SEQ1: R39.1 R40.1 R41.1 R42.1 R43.1 U3.21(EN2) ; off-sheet EN2_SEQ1
EN2_SEQ2: R63.1 U5.21(EN2)
EN3_SEQ1: R45.1 U3.20(EN3)
EN3_SEQ2: R65.1 U5.20(EN3)
EN4_SEQ1: R47.1 U3.19(EN4)
EN_0V80: R45.2 TP25.1 U9.1(1A) ; off-sheet EN_0V80
EN_0V92: R61.2 TP30.1 U11.3(ON) ; off-sheet EN_0V92
EN_1V2: R65.2 TP32.1 U12.3(ON) ; off-sheet EN_1V2
EN_1V2_MEM: R42.2 TP22.1 ; off-sheet EN_1V2_MEM
EN_1V2_VCCO: R40.2 TP20.1 U10.3(ON) ; off-sheet EN_1V2_VCCO
EN_1V5: R47.2 TP26.1 U7.3(ON) ; off-sheet EN_1V5
EN_1V5_GTY: R63.2 TP31.1 U8.3(ON) ; off-sheet EN_1V5_GTY
EN_2V5_DDR: R41.2 TP21.1 ; off-sheet EN_2V5_DDR
EN_3V3_VCCO: R39.2 TP19.1 U6.3(ON) ; off-sheet EN_3V3_VCCO
EN_12V0_SYS: TP23.1 U3.22(EN1) U4.3(ON) ; off-sheet EN_12V0_SYS
EN_DDR_VTT: R43.2 TP24.1 ; off-sheet EN_DDR_VTT
FAULT_SEQ: R53.1 R68.1 TP28.1 U3.7(~{FAULT}) U5.7(~{FAULT}) ; off-sheet FAULT_SEQ
HYS_SEQ1: R56.2 U3.6(HYS)
HYS_SEQ2: R71.2 U5.6(HYS)
PGOOD_6003_0V8: R54.1 ; off-sheet PGOOD_6003_0V8
REFCAP_SEQ1: C86.1 U3.5(REFCAP)
REFCAP_SEQ2: C91.1 U5.5(REFCAP)
REG_SEQ1: R58.2 U3.10(REG_TMR)
REG_SEQ2: R73.2 U5.10(REG_TMR)
SYS_READY: U5.13(PWRGD) ; off-sheet SYS_READY
SYS_RESTART: C85.1 R59.1 R60.2 SW1.1 TP29.1 U3.8(UP) ; off-sheet SYS_RESTART
SYS_SEQ_DOWN: R74.1 R75.2 U5.16(~{DOWN}) ; off-sheet SYS_SEQ_DOWN
VLDO_SEQ1: C83.1 R53.2 U3.15(VLDO)
VLDO_SEQ2: C90.2 R68.2 U5.4(SENSE4) U5.15(VLDO)
NetQ6_1: Q6.1(G) R77.2 R78.2
NetQ6_2: Q6.2(D) R76.1
NetR44_1: R44.1 R50.2 TP27.1 U3.1(SENSE1) U4.5(QOD)
NetR46_1: R46.1 R51.2 U3.2(SENSE2)
NetR48_1: R48.1 R52.2 R54.2 U3.3(SENSE3)
NetR49_1: R49.1 R55.2 U3.4(SENSE4)
NetR62_1: R62.1 R67.2 U5.1(SENSE1)
NetR64_1: R64.1 R69.2 U5.2(SENSE2)
NetR66_1: R66.1 R70.2 U5.3(SENSE3)
NetR77_1: R77.1 U9.2(1Y)
NetU3_12: U3.12(SEQ_DONE) U5.8(UP)
NetU3_16: U3.16(~{DOWN}) U5.12(SEQ_DONE)

Not connected (* = marked no-connect by the designer): U3 13(PWRGD); U4 6(OUT); U5 19(EN4); U6 6(OUT); U7 6(OUT); U8 6(OUT); U9 4(2Y) 6(3Y) 8(4Y) 10(5Y) 12(6Y); U10 6(OUT); U11 6(OUT); U12 6(OUT)

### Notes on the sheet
- Sequencing
- Main sequencing
  PL, SPD, and FPD
- Monitoring 3V3_VCCO. Could instead monitor 1V2_VCCO.
  Don't monitor 2V5_DDR, 1V2_MEM, or DDR_VTT since no pull-down
- (1.4ms)
- (near R58) (19.6ms)
- (near SW1) Disable seq
- (near R73) (19.6ms)
- Discharge Circuitry - Other Rails
- Discharge Circuitry - Core Rail
- 0.3ohms, ~
  0ms discharge, 2.3A peak

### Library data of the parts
C80-C83 C87-C90 = CMP-0085980-1: as C26 on sheet TIDA-050088_Core
C84 C92-C94 C96-C98 = CMP-0006946-4: as C68 on sheet TIDA-050088_Core
C85 = CMP-0007750-2: CAP, CERM, 1.5 uF, 10 V, +/- 10%, X7R, 0805; Manufacturer: Kemet; TaMin_C: -55°C; ESR_ohm: 9m; Polarized: N; SizeAreaWB_mm2: 6.75; Value1: 0.009 ohm; U/M: EA; Value: 1.5uF; TaMax_C: 125°C; SizeZ_mm: 1.45; SizeX_mm: 2; SizeY_mm: 1.25; Cap_Case: 0805; SizeArea_mm2: 2.5; IRMS_A: 12.74A; AEC Category: Q200
C86 C91 = CMP-0007674-2: CAP, CERM, 0.47 uF, 16 V, +/- 5%, X7R, 0805; Manufacturer: AVX; TaMin_C: -55°C; ESR_ohm: 11m; Polarized: N; SizeAreaWB_mm2: 6.75; Value1: 0.011 ohm; U/M: EA; Value: 0.47uF; TaMax_C: 125°C; SizeZ_mm: 1.45; SizeX_mm: 2; SizeY_mm: 1.25; Cap_Case: 0805; SizeArea_mm2: 2.5; AEC Category: Q200
C95 = CMP-0006979-5: as C42 on sheet TIDA-050088_Core
Q6 = CMP-0122642-1: Rad Hard e-GaN 40 V, 8 A, 28 mΩ Surface Mount (FSMD-A); Manufacturer: EPC SPACE; AEC Qualified: No; IdsMax_A: 8A; QgTyp_nC: 2.2nC @ 5V; Rdson45_ohm: 24m; SizeZ_mm: 2.286mm; VdsMax_V: 40V; Vgs_V: 6V; ChMode: False; Input Capacitace At Vds: 283pF @ 20V; Number Of Channels: 1; Pulse Drain Current: 32A; Reverse Recovery Charge: 1nC; Rthja Max: 40°C/W; Threshold Vgs Max: 2.5V; Threshold Vgs Min: 0.8V; TJmax_C: +150°C
R39-R43 R45 R47 R61 R63 R65 = CMP-0025823-4: RES, 510, 5%, 0.1 W, AEC-Q200 Grade 0, 0603; Manufacturer: Vishay-Dale; Power_W: 100mW; TempCo: 200 ppm/C; Value_Code: 510R; Value: 510; EIA_Code: E24; SizeX_mm: 1.6; SizeY_mm: 0.8; SizeZ_mm: 1; Value2: 0.1W; SizeArea_mm2: 1.28; AEC Qualified: Y; VDC_V: 75V; AEC Category: Q200; AEC Grade: 0
R44 = CMP-0024346-2: RES 56.9K OHM 0.5% 1/10W 0603; Value_Code: 56k9
R46 = CMP-0023674-3: RES, 118 k, 0.1%, 0.1 W, 0603; Manufacturer: Yageo America; Power_W: 100mW; TempCo: 25 ppm/C; U/M: EA; Value: 118k; EIA_Code: E192; SizeX_mm: 1.6; SizeY_mm: 0.8; SizeZ_mm: 1; Value2: 0.1W; SizeArea_mm2: 1.28; VDC_V: 75V; AEC Category: Q200
R48 = CMP-0024051-3: RES, 29.4 k, 0.1%, 0.1 W, 0603; Manufacturer: Yageo America; Power_W: 100mW; TempCo: 25 ppm/C; Value_Code: 29k4; U/M: EA; Value: 29.4k; EIA_Code: E192; SizeX_mm: 1.6; SizeY_mm: 0.8; SizeZ_mm: 1; Value2: 0.1W; SizeArea_mm2: 1.28; VDC_V: 75V; AEC Category: Q200
R49 R64 = CMP-0024333-2: RES 54.2K OHM 0.1% 0.21W 0603; Manufacturer: Vishay Dale; Value_Code: 54k2
R50 = CMP-0024201-2: RES, 3.61 k, 0.1%, 0.1 W, 0603; Manufacturer: Yageo America; Power_W: 100mW; TempCo: 25 ppm/C; Value_Code: 3k61; U/M: EA; Value: 3.61k; EIA_Code: E192; SizeX_mm: 1.6; SizeY_mm: 0.8; SizeZ_mm: 1; Value2: 0.1W; SizeArea_mm2: 1.28; VDC_V: 75V; AEC Category: Q200
R51 = CMP-0024039-3: RES, 28.7 k, 0.1%, 0.1 W, 0603; Manufacturer: Yageo America; Power_W: 100mW; TempCo: 25 ppm/C; Value_Code: 28k7; U/M: EA; Value: 28.7k; EIA_Code: E192; SizeX_mm: 1.6; SizeY_mm: 0.8; SizeZ_mm: 1; Value2: 0.1W; SizeArea_mm2: 1.28; VDC_V: 75V; AEC Category: Q200
R52 = CMP-0023664-2: RES 111K OHM 0.1% 1/10W 0603; Manufacturer: KOA Speer Electronics, Inc.
R53 R68 R78 = CMP-0023392-3: as R2 on sheet TIDA-050088_Core
R54 R77 = CMP-0081973-1: as R5 on sheet TIDA-050088_Core
R55 R69 = CMP-0024214-3: as R7 on sheet TIDA-050088_Core
R56 R71 = CMP-0023563-3: RES, 49.9 k, 0.1%, 0.1 W, 0603; Manufacturer: Susumu Co Ltd; Power_W: 100mW; TempCo: 25 ppm/C; Value_Code: 49k9; U/M: EA; Value: 49.9k; EIA_Code: E192; SizeX_mm: 1.6; SizeY_mm: 0.8; SizeZ_mm: 1; Value2: 0.1W; SizeArea_mm2: 1.28; VDC_V: 75V; AEC Category: Q200
R57 R72 = CMP-0025493-3: RES, 65.7 k, 0.5%, 0.1 W, 0603; Manufacturer: Yageo America; Power_W: 100mW; TempCo: 50 ppm/C; Value_Code: 65k7; U/M: EA; Value: 65.7k; EIA_Code: E192; SizeX_mm: 1.6; SizeY_mm: 0.8; SizeZ_mm: 1; Value2: 0.1W; SizeArea_mm2: 1.28; VDC_V: 75V; AEC Category: Q200
R58 R73 = CMP-0023328-4: RES, 976 k, 1%, 0.1 W, 0603; Manufacturer: Yageo; Power_W: 100mW; TempCo: 100 ppm/C; Value: 976k; EIA_Code: E96; SizeX_mm: 1.6; SizeY_mm: 0.8; SizeZ_mm: 1; Value2: 0.1W; SizeArea_mm2: 1.28; AEC Qualified: N; VDC_V: 75V; AEC Category: Q200; SizeAreaWB_mm2: 4.68
R59 R74 = CMP-0023928-2: RES SMD 20K OHM 0.1% 1/10W 0603; Manufacturer: Panasonic Electronic Components
R60 = CMP-0023431-3: RES, 1.30 k, 0.1%, 0.1 W, 0603; Manufacturer: Susumu Co Ltd; Power_W: 100mW; TempCo: 25 ppm/C; Value_Code: 1k30; U/M: EA; Value: 1.30k; EIA_Code: E192; Res_ohm: 1.3k; SizeX_mm: 1.6; SizeY_mm: 0.8; SizeZ_mm: 1; Value2: 0.1W; SizeArea_mm2: 1.28; VDC_V: 75V; AEC Category: Q200
R62 = CMP-0024127-2: RES 34K OHM 0.1% 1/10W 0603; Manufacturer: KOA Speer Electronics, Inc.
R66 = CMP-0024247-2: RES SMD 44.2KOHM 0.1% 1/10W 0603; Manufacturer: Yageo; Value_Code: 44k2; Value: 44.2k
R67 = CMP-0024461-3: RES, 75.0 k, 0.1%, 0.1 W, 0603; Manufacturer: Yageo America; Power_W: 100mW; TempCo: 25 ppm/C; Value_Code: 75k0; U/M: EA; Value: 75.0k; EIA_Code: E192; Res_ohm: 75k; SizeX_mm: 1.6; SizeY_mm: 0.8; SizeZ_mm: 1; Value2: 0.1W; SizeArea_mm2: 1.28; VDC_V: 75V; AEC Category: Q200
R70 = CMP-0024283-3: RES SMD 49.3KOHM 0.1% 1/10W 0603; Manufacturer: Yageo; Value_Code: 49k3; Value: 49.3k
R75 = CMP-0023868-3: RES SMD 1.1K OHM 0.1% 1/10W 0603; Manufacturer: Panasonic Electronic Components; Value_Code: 1k1
R76 = CMP-0016527-2: RES, 0.3, 1%, 1 W, 2010; Manufacturer: Stackpole Electronics Inc; Power_W: 1W; TempCo: 250 ppm/C; Value_Code: R300; U/M: EA; Value: 0.3; EIA_Code: E96; SizeX_mm: 5; SizeY_mm: 2.5; SizeZ_mm: 1.66; SizeArea_mm2: 12.5; AEC Category: Q200
SW1 = CMP-0086077-1: Dip Switch SPST 1 Position Through Hole Slide (Standard) Actuator 25mA 24VDC; Manufacturer: Omron Electronics Inc-EMC Div; SizeZ_mm: 6.7mm; PositionCount: 1
TP19-TP32 = CMP-0055149-2: as TP1 on sheet TIDA-050088_Core
U3 U5 = CMP-0097863-4: Radiation-Hardeness-Assured, 14-V, 4-Channel Sequencer; Manufacturer: Texas Instruments; CompType: IC; AEC Category: Q200; Max Supply Voltage: 14V; Standoff Height: 0.555mm; AEC Qualified: No; SizeZ_mm: 2.428mm; Number Of Outputs: 4; Min Supply Voltage: 3V; TJmax_C: +125°C; Nominal Supply Current: 2mA
U4 U6-U8 U10-U12 = CMP-0095470-2: Radiation-tolerant, 1.6-V to 5.5-V, 1.25-A 90-mΩ load switch; Manufacturer: Texas Instruments; Rise Time: 1280us; AEC Qualified: No; TaMin_C: -40°C; CompType: IC; Number Of Outputs: 1; Max Supply Voltage: 5.5V; Turn On Delay Time: 1950us; Turn Off Delay Time: 6us; Min Supply Voltage: 1.6V; TJmax_C: +125°C; AEC Category: Q200; SizeZ_mm: 1.1mm; Standoff Height: 0mm; Fall Time: 4ms
U9 = CMP-0122772-1: Radiation-tolerant six-bit inverting fixed-direction level translator with Schmitt-trigger inputs; Manufacturer: Texas Instruments; SizeZ_mm: 1.2mm; AEC Qualified: No; Max Supply Voltage: 5.5V; Min Supply Voltage: 1.2V; Nominal Supply Current: 2uA; Number Of Inputs: 1; PositionCount: 6; Propagation Delay: 7.1ns; Standoff Height: 0.05mm; TaMax_C: +125°C; TaMin_C: -55°C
